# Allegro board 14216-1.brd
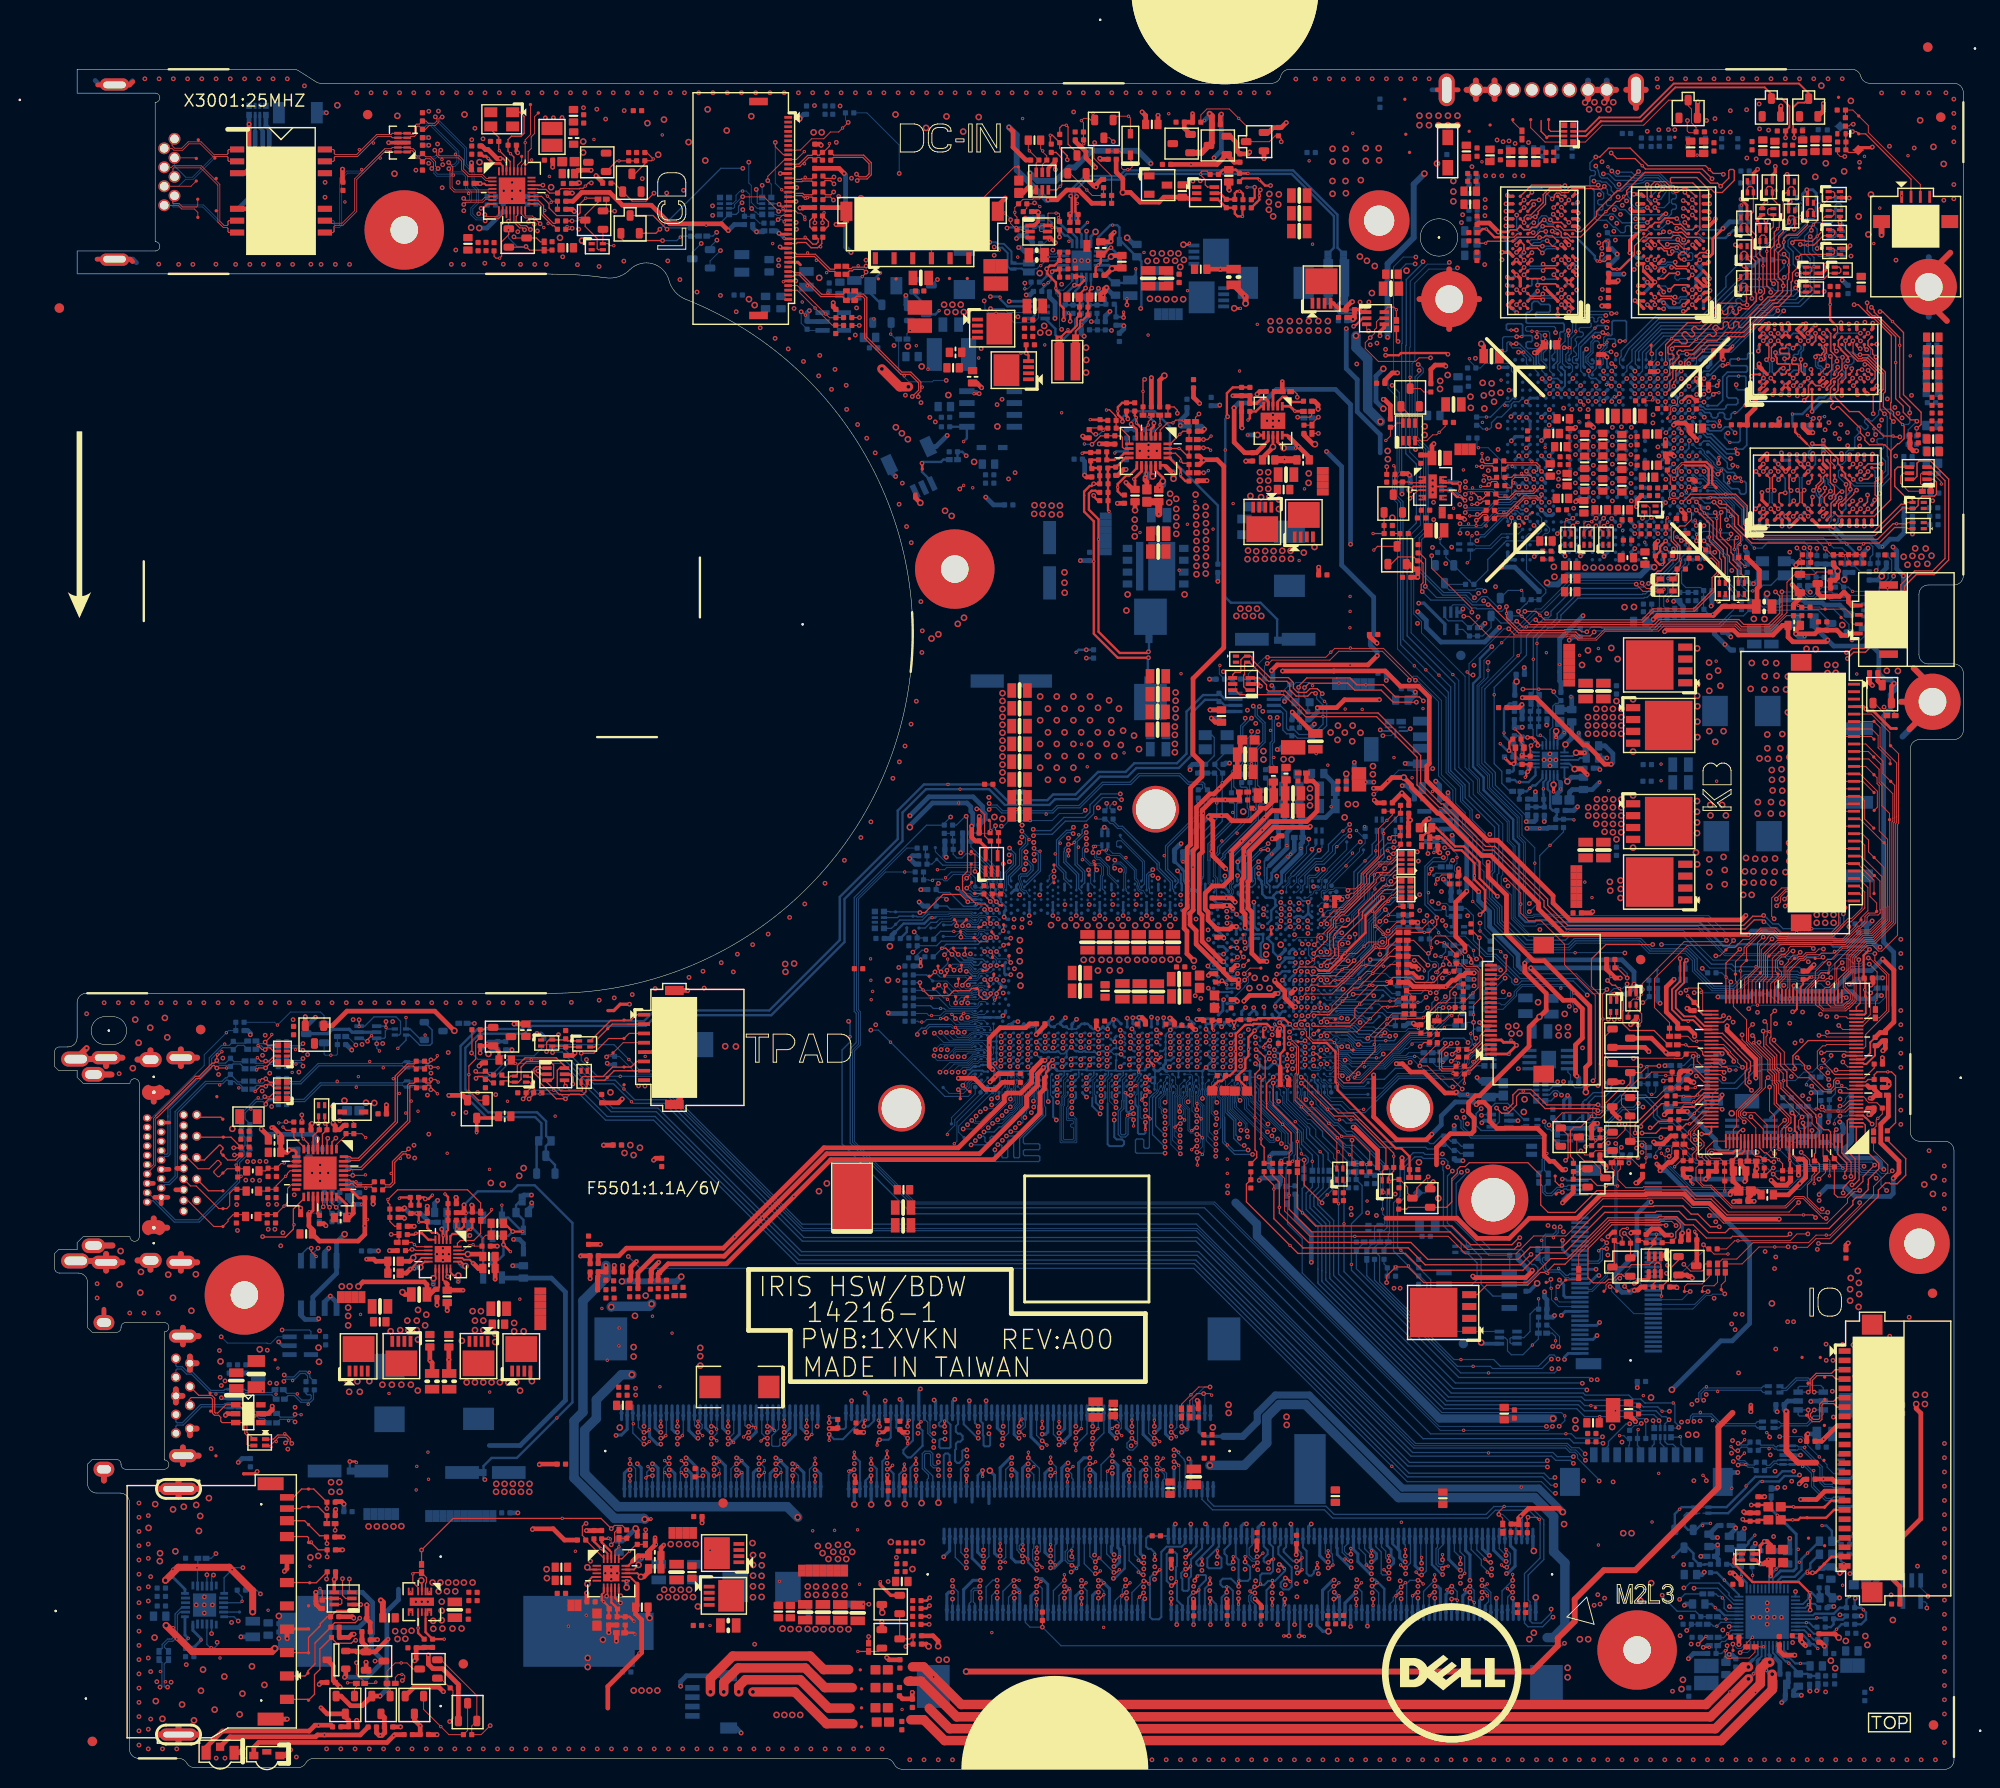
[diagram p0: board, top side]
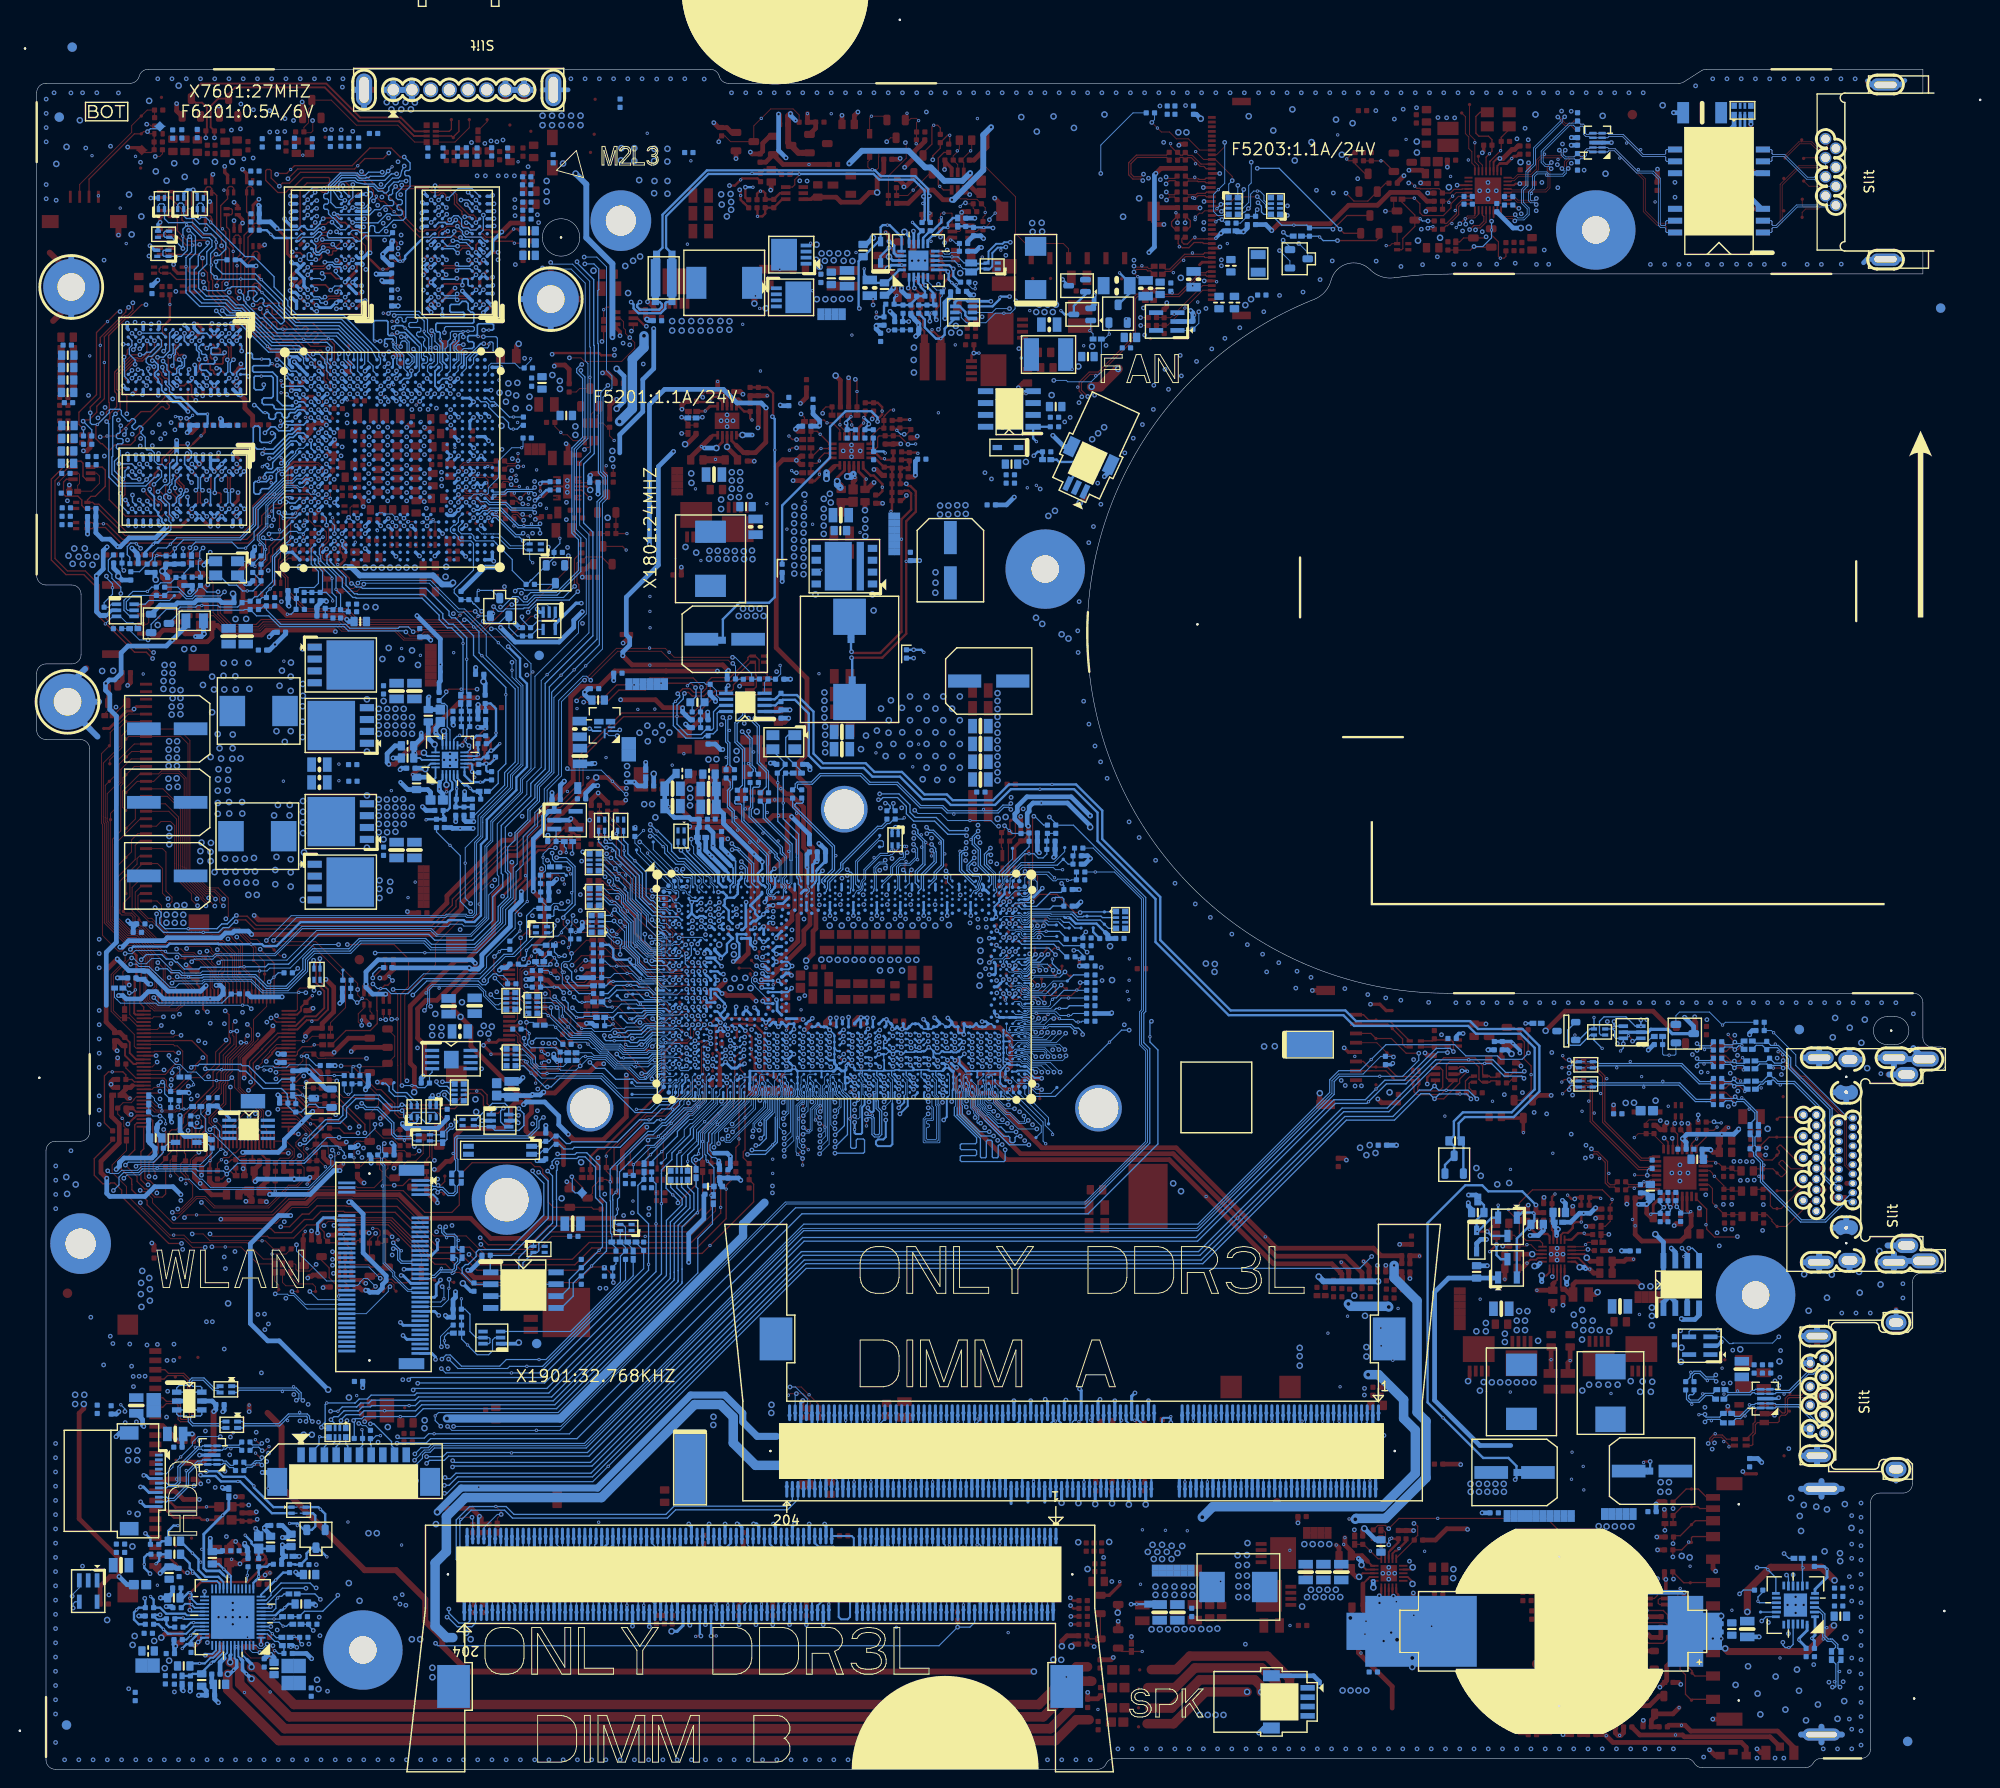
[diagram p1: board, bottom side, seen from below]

Outline 204.2 x 181.97 mm; copper layers: TOP, L2VCC, L3, L4, L5GND, BOTTOM. Coordinates in mm from the lower left corner of the outline.
Outline path: 0,76.82 0,75.22 0.4,74.82 2.4,74.82 2.4,74.07 3.05,73.42 8.05,73.42 arc(8.55,73.92) 9.05,73.42 9.05,57.02 arc(8.55,56.52) 8.05,57.02 3.05,57.02 2.4,56.37 2.4,55.62 0.4,55.62 0,55.22 0,53.62 arc(0.15,53.27) 0.5,53.12 2.52,53.12 arc(3.23,52.83) 3.52,52.12 3.52,47.27 4.02,46.77 6.6,46.77 arc(6.97,46.93) 7.1,47.32 arc(7.25,47.67) 7.6,47.82 11.72,47.82 arc(12.22,47.32) 11.72,46.82 11.72,33.12 arc(12.22,32.62) 11.72,32.12 7.6,32.12 arc(7.25,32.27) 7.1,32.62 arc(6.97,33.01) 6.6,33.17 4.02,33.17 3.52,32.67 3.52,30.57 arc(3.81,29.86) 4.52,29.57 7,29.57 arc(7.71,29.28) 8,28.57 8,2.17 arc(8.29,1.46) 9,1.17 13.27,1.17 arc(13.77,1.04) 14.13,0.67 arc(14.5,0.3) 15,0.17 26,0.17 arc(26.5,0.3) 26.87,0.67 arc(27.23,1.04) 27.73,1.17 88.88,1.17 arc(89.42,1.01) 89.79,0.58 arc(90.16,0.16) 90.7,0 202.2,0 arc(202.91,0.29) 203.2,1 203.2,66.23 arc(202.91,66.94) 202.2,67.23 199.53,67.23 arc(198.82,67.52) 198.53,68.23 198.53,109.23 arc(198.82,109.94) 199.53,110.23 203.2,110.23 arc(203.91,110.52) 204.2,111.23 204.2,117.32 arc(203.91,118.03) 203.2,118.32 200.45,118.32 arc(199.74,118.61) 199.45,119.32 199.45,125.77 arc(199.74,126.48) 200.45,126.77 203.2,126.77 arc(203.91,127.06) 204.2,127.77 204.2,179.47 arc(203.91,180.18) 203.2,180.47 194.2,180.47 arc(193.59,180.68) 193.23,181.22 arc(192.88,181.76) 192.26,181.97 132.14,181.97 arc(131.52,181.76) 131.17,181.22 arc(130.81,180.68) 130.2,180.47 28.49,180.47 arc(28.21,180.51) 27.95,180.63 26.1,181.81 arc(25.84,181.93) 25.56,181.97 2.4,181.97 2.4,179.42 10.75,179.42 arc(11.25,178.92) 10.75,178.42 10.75,163.52 arc(11.25,163.02) 10.75,162.52 2.4,162.52 2.4,160.07 52.55,160.07 arc(52.93,160.06) 53.3,160.04 arc(56.13,159.95) 58.95,159.65 arc(60.34,159.77) 61.52,160.51 arc(63.95,161.16) 65.72,159.38 arc(66.37,158.15) 67.51,157.35 arc(91.11,114.33) 53.3,83.07 arc(52.93,83.06) 52.55,83.07 3.4,83.07 arc(2.69,82.78) 2.4,82.07 2.4,78.32 arc(2.11,77.61) 1.4,77.32 0.5,77.32 arc(0.15,77.17) 0,76.82 ; 5.4,80.57 6.2,80.57 arc(7.7,79.07) 6.2,77.57 5.4,77.57 arc(3.9,79.07) 5.4,80.57 ; 18.85,50.77 arc(20.3,52.22) 21.75,50.77 arc(20.3,49.32) 18.85,50.77 ; 35.95,164.77 arc(37.4,166.22) 38.85,164.77 arc(37.4,163.32) 35.95,164.77 ; 88.5,70.77 arc(90.6,72.87) 92.7,70.77 arc(90.6,68.67) 88.5,70.77 ; 94.85,128.47 arc(96.3,129.92) 97.75,128.47 arc(96.3,127.02) 94.85,128.47 ; 115.7,102.77 arc(117.8,104.87) 119.9,102.77 arc(117.8,100.67) 115.7,102.77 ; 140.1,165.77 arc(141.7,167.37) 143.3,165.77 arc(141.7,164.17) 140.1,165.77 ; 142.9,70.77 arc(145,72.87) 147.1,70.77 arc(145,68.67) 142.9,70.77 ; 146.1,163.97 arc(148.1,165.97) 150.1,163.97 arc(148.1,161.97) 146.1,163.97 ; 151.6,60.97 arc(153.9,63.27) 156.2,60.97 arc(153.9,58.67) 151.6,60.97 ; 167.85,12.77 arc(169.3,14.22) 170.75,12.77 arc(169.3,11.32) 167.85,12.77 ; 197.9,56.27 arc(199.5,57.87) 201.1,56.27 arc(199.5,54.67) 197.9,56.27

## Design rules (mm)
constraint set DEFAULT: min track width 0.127, pair gap 0.102
net group AUDIO_12MIL: nets CPVEE V3D3_STB
net group CLK_PCI_KBC: nets CLK_PCI_KBC CLK_PCI_KBC_R
net group CLK_PCI_LPC: nets CLK_PCI_LPC CLK_PCI_LPC_R
net group CODEC_BITCLK_R: nets CODEC_BITCLK_R HDA_CODEC_BITCLK
net group CODEC_SDOUT_R: nets CODEC_SDOUT_R HDA_CODEC_SDOUT
net group CPU_RXN_C_DGPU_TXN0: nets CPU_RXN_C_DGPU_TXN0 DGPU_TXN_CPU_RXN0
net group CPU_RXN_C_DGPU_TXN1: nets CPU_RXN_C_DGPU_TXN1 DGPU_TXN_CPU_RXN1
net group CPU_RXN_C_DGPU_TXN2: nets CPU_RXN_C_DGPU_TXN2 DGPU_TXN_CPU_RXN2
net group CPU_RXN_C_DGPU_TXN3: nets CPU_RXN_C_DGPU_TXN3 DGPU_TXN_CPU_RXN3
net group CPU_RXP_C_DGPU_TXP0: nets CPU_RXP_C_DGPU_TXP0 DGPU_TXP_CPU_RXP0
net group CPU_RXP_C_DGPU_TXP1: nets CPU_RXP_C_DGPU_TXP1 DGPU_TXP_CPU_RXP1
net group CPU_RXP_C_DGPU_TXP2: nets CPU_RXP_C_DGPU_TXP2 DGPU_TXP_CPU_RXP2
net group CPU_RXP_C_DGPU_TXP3: nets CPU_RXP_C_DGPU_TXP3 DGPU_TXP_CPU_RXP3
net group CRT_B: nets CRT_B DP_CRT_B
net group CRT_G: nets CRT_G DP_CRT_G
net group CRT_HSYNC_CON: nets CRT_HSYNC_CON DP_CRT_HSYNC_CON
net group CRT_R: nets CRT_R DP_CRT_R
net group CRT_VSYNC_CON: nets CRT_VSYNC_CON DP_CRT_VSYNC_CON
net group DDR3_A_ODT10: nets M_A_DIMA_ODT0 M_A_DIMA_ODT1
net group DDR3_B_ODT10: nets M_B_DIMB_ODT0 M_B_DIMB_ODT1
net group DGPU_RXN_CPU_TXN0: nets DGPU_RXN_C_CPU_TXN0 DGPU_RXN_CPU_TXN0
net group DGPU_RXN_CPU_TXN1: nets DGPU_RXN_C_CPU_TXN1 DGPU_RXN_CPU_TXN1
net group DGPU_RXN_CPU_TXN2: nets DGPU_RXN_C_CPU_TXN2 DGPU_RXN_CPU_TXN2
net group DGPU_RXN_CPU_TXN3: nets DGPU_RXN_C_CPU_TXN3 DGPU_RXN_CPU_TXN3
net group DGPU_RXP_CPU_TXP0: nets DGPU_RXP_C_CPU_TXP0 DGPU_RXP_CPU_TXP0
net group DGPU_RXP_CPU_TXP1: nets DGPU_RXP_C_CPU_TXP1 DGPU_RXP_CPU_TXP1
net group DGPU_RXP_CPU_TXP2: nets DGPU_RXP_C_CPU_TXP2 DGPU_RXP_CPU_TXP2
net group DGPU_RXP_CPU_TXP3: nets DGPU_RXP_C_CPU_TXP3 DGPU_RXP_CPU_TXP3
net group EDP_AUX: nets EDP_AUX EDP_AUX_DP
net group EDP_AUX#: nets EDP_AUX# EDP_AUX_DN
net group EDP_TX0: nets EDP_TX0 EDP_TX0_DP
net group EDP_TX0#: nets EDP_TX0# EDP_TX0_DN
net group EDP_TX1: nets EDP_TX1 EDP_TX1_DP
net group EDP_TX1#: nets EDP_TX1# EDP_TX1_DN
net group FAN_TACH: nets FAN_TACH1 FAN_TACH1_C
net group FBA_VREF: nets FBA_VREF_0 FBA_VREF_1
net group H_CPU_SVIDCLK: nets H_CPU_SVIDCLK PWR_VCC_SCLK
net group H_CPU_SVIDDAT: nets H_CPU_SVIDDAT PWR_VCC_SDA
net group LAN_TXN_C_PCH_RXN4: nets LAN_TXN_C_PCH_RXN4 PCIE_PRX_LANTX_N4
net group LAN_TXP_C_PCH_RXP4: nets LAN_TXP_C_PCH_RXP4 PCIE_PRX_LANTX_P4
net group PCH_DPB_AUXN: nets PCH_DPB_AUXN PCH_DPC_AUXN_U
net group PCH_DPB_AUXP: nets PCH_DPB_AUXP PCH_DPC_AUXP_U
net group PCIE_PRX_WLANTX_N3: nets PCIE_PRX_WLANTX_N3 PCIE_PRX_WLANTX_N3_R
net group PCIE_PRX_WLANTX_P3: nets PCIE_PRX_WLANTX_P3 PCIE_PRX_WLANTX_P3_R
net group PCIE_PTX_LANRX_N4: nets PCIE_PTX_LANRX_N4 PCIE_PTX_LANRX_N4_C
net group PCIE_PTX_LANRX_P4: nets PCIE_PTX_LANRX_P4 PCIE_PTX_LANRX_P4_C
net group PCIE_PTX_WLANRX_N3: nets PCIE_PTX_WLANRX_N3 PCIE_PTX_WLANRX_N3_C
net group PCIE_PTX_WLANRX_P3: nets PCIE_PTX_WLANRX_P3 PCIE_PTX_WLANRX_P3_C
net group PECI-MW: nets H_PECI PECI
net group POWER_15M: nets Q6205_Q TP_ON#_S
net group PWR_VCC_FB: nets PWR_VCC_FB VCC_SENSE
net group REF10M: nets KBC_VCORF PROC_OPI_COMP3
net group SATA_PRX_ODDTX_N1: nets SATA_PRX_ODDTX_N1 SATA_RXN2_R
net group SATA_PRX_ODDTX_P1: nets SATA_PRX_ODDTX_P1 SATA_RXP2_R
net group SATA_PTX_ODDRX_N1: nets SATA_PTX_ODDRX_N1 SATA_TXN2_R
net group SATA_PTX_ODDRX_P1: nets SATA_PTX_ODDRX_P1 SATA_TXP2_R
net group SD_CD#: nets SD_CD# SD_CD_R#
net group SD_CLK: nets SD_CLK SD_CLK_5170
net group SD_WP: nets SD_WP SD_WP_5170
net group T8-MW: nets VD_IN1 VD_IN1_C
net group THERM_10M: nets FON# VD1_EN#
net group USB3_PTX_CRX_N0: nets USB3_PTX_CRX_N0 USB3_PTX_CRX_N0_R
net group USB3_PTX_CRX_P0: nets USB3_PTX_CRX_P0 USB3_PTX_CRX_P0_R
net group USB_CAMERA_EDP: nets USB_CAMERA_EDP USB_PP4
net group USB_CAMERA_EDP#: nets USB_CAMERA_EDP# USB_PN4
net group USB_PN0: nets USB_PN0 USB_PN0_C
net group USB_PN5: nets USB_PN5 USB_PN5_R
net group USB_PN6: nets USB_PN6 USB_PN6_TPNL
net group USB_PN7: nets USB_PN7 USB_PN7_R
net group USB_PP0: nets USB_PP0 USB_PP0_C
net group USB_PP5: nets USB_PP5 USB_PP5_R
net group USB_PP6: nets USB_PP6 USB_PP6_TPNL
net group USB_PP7: nets USB_PP7 USB_PP7_R
net group AUDIO_BEEP_10MIL: nets AUD_HP1_JACK_L AUD_HP1_JACK_L1 AUD_HP1_JACK_R AUD_HP1_JACK_R1 AUD_PC_BEEP AUD_PC_BEEP_C AUD_PORTA_L_R_B AUD_PORTA_R_R_B AUD_SENSE AUD_SENSE_A AUD_VREF CBN HDA_SPKR HDA_SPKR_R JACK_PLUG KBC_BEEP KBC_BEEP_R LINE1-L_C LINE1-L_R LINE1_L LINE1_R LINE1_VREFO_L LINE1_VREFO_R MIC2_VREFO
net group CARD_12MIL: nets RREF RSET SDREFG V18
net group CFG-MW: nets CFG0 CFG1 CFG2 CFG3 CFG4 CFG5 CFG6 CFG7 CFG8 CFG9 CFG10 CFG11 CFG12 CFG13 CFG14 CFG15 CFG16 CFG17 CFG18 CFG19
net group CL-MW: nets TP_CL_CLK TP_CL_DATA TP_CL_RST#
net group CLK-MW: nets CLK_DP2VGA PEXTSTCLK_OUT PEXTSTCLK_OUT# SUS_CLK SUS_CLK_PCH SUSCLK_KBC VIDEO_CLK_XTAL_SS
net group COMP_20MIL: nets CFG_RCOMP EDP_COMP PCH_OPIRCOMP PCIE_RCOMP PROC_OPI_COMP SATA_IREF SATA_RCOMP SM_RCOMP_0 SM_RCOMP_1 SM_RCOMP_2 TD_IREF USB_COMP XCLK_BIASREF
net group CPU-MW: nets H_PROCHOT# H_PROCHOT#_EC H_PROCHOT#_R PQ4405_3 PROCHOT_EC VGA_CORE_VID
net group DDC_CLK_HDMI: nets DDC_CLK_HDMI
net group DDC_DATA_HDMI: nets DDC_DATA_HDMI
net group GND: nets GND_R1 GND_R2 MIC_GND
net group H_CPU_SVIDALRT#: nets H_CPU_SVIDALRT# PWR_VCC_ALERT# VR_SVID_ALERT#
net group HDA_CODEC_RST#: nets HDA_CODEC_RST#
net group HDA_CODEC_SDIN0: nets HDA_SDIN0
net group HDA_CODEC_SYNC: nets HDA_CODEC_SYNC
net group HDMI_CLK: nets HDMI_CLK HDMI_CLK_R HDMI_CLK_R_C
net group HDMI_CLK#: nets HDMI_CLK# HDMI_CLK#_R HDMI_CLK#_R_C
net group HDMI_CRT_N0: nets HDMI_CRT_N0 HDMI_DATA2# HDMI_DATA2#_R HDMI_DATA2#_R_C PCH_DPC_N0_U
net group HDMI_CRT_N1: nets HDMI_CRT_N1 HDMI_DATA1# HDMI_DATA1#_R HDMI_DATA1#_R_C PCH_DPC_N1_U
net group HDMI_CRT_P0: nets HDMI_CRT_P0 HDMI_DATA2 HDMI_DATA2_R HDMI_DATA2_R_C PCH_DPC_P0_U
net group HDMI_CRT_P1: nets HDMI_CRT_P1 HDMI_DATA1 HDMI_DATA1_R HDMI_DATA1_R_C PCH_DPC_P1_U
net group HDMI_DATA0: nets HDMI_DATA0 HDMI_DATA0_R HDMI_DATA0_R_C
net group HDMI_DATA0#: nets HDMI_DATA0# HDMI_DATA0#_R HDMI_DATA0#_R_C
net group JTAG: nets PCH_JTAG_TCK PCH_JTAG_TDI PCH_JTAG_TDO PCH_JTAG_TMS PCH_JTAG_TRST#
net group KB: nets KB_BL_CTRL KCOL0 KCOL1 KCOL2 KCOL3 KCOL4 KCOL5 KCOL6 KCOL7 KCOL8 KCOL9 KCOL10 KCOL11 KCOL12 KCOL13 KCOL14 KCOL15 KCOL16 KROW0 KROW1 KROW2 KROW3 KROW4 KROW5 KROW6 KROW7
net group LAN_MDI0N: nets MDO0-
net group LAN_MDI0P: nets MDO0+
net group LAN_MDI1N: nets MDO1-
net group LAN_MDI1P: nets MDO1+
net group LAN_MDI2N: nets MDO2-
net group LAN_MDI2P: nets MDO2+
net group LAN_MDI3N: nets MDO3-
net group LAN_MDI3P: nets MDO3+
net group LCD_BKLT-MW: nets BKLT_CTRL EC_BRIGHTNESS EDP_BKLT_CTRL EDP_BRIGHTNESS L_BKLT_CTRL LCD_BRIGHTNESS
net group LED: nets BATT_WHITE_LED# BATT_WHITE_LED_R# CAP_LED# CAP_LED_R# CHG_AMBER_LED# CHG_AMBER_LED_R# SATA_LED# SATA_LED#_B SATA_LED#_R
net group LED_20MIL: nets AMBER_LED_BAT BAT_AMBER BAT_WHITE CAP_LED CAP_LED_Q SATA_LED SATA_LED_R WHITE_LED_BAT
net group LPC-MWS: nets INT_SERIRQ LPC_AD0 LPC_AD1 LPC_AD2 LPC_AD3 LPC_FRAME# LPC_FRAME#_DEBUG LPC_LAD0_PCH LPC_LAD0_R LPC_LAD1_PCH LPC_LAD1_R LPC_LAD2_PCH LPC_LAD2_R LPC_LAD3_PCH LPC_LAD3_R LPC_LFRAME#_PCH
net group OTHER_4MIL: nets 1D05V_VGA_S0_DISCHG AC_IN# AC_PRESENT AD+_G_1 AD_IA AD_IA_HW AD_IA_HW2 ALERT# AMP_MUTE# BAT_IN# BATLOW# BLON_OUT BLON_OUT_C BLUETOOTH_EN BLUETOOTH_EN_NGFF BOARD_ID2 BOARD_ID3 BUFRST# CAMERA_PWR_EN CARD_PWR_EN CLK_PCIE_WLAN_REQ3# CLK_PCIE_WLAN_REQ# COLOR_ENGINE COMBO-GPI CPU_ID CRT_PCH_HPD DBC_EN DBC_EN_R DC_TEST_A3_B3 DC_TEST_A61_B61 DC_TEST_AY2_AW2 DC_TEST_AY3_AW3 DC_TEST_AY61_AW61 DC_TEST_AY62_AW62 DC_TEST_B62_B63 DC_TEST_C1_C2 DGPU_PWR_EN# DSWODVREN E51_RX1 E51_RX2 E51_TX1 E51_TX2 E51_TXD EAPD# EC_SCI# EC_SMI# EC_SWI# ECRST# ECSCI#_KBC ECSMI#_KBC ECSWI#_KBC EDP_HPD EDP_HPD_CONN EDP_SPARE FB_VREF FBA_DEBUG0 FBA_DEBUG1 H_CATERR# H_RCIN# H_THERMTRIP# H_THERMTRIP_EN HDD_DEVSLP HDD_DEVSLP_R HDMI_CRT_DET HDMI_HPD_B HDMI_HPD_E HPD_HDMI_CON HSIOPC HSIOPC_R HVM_CLK HVM_CLK# IFPAB_IOVDD IFPAB_PLLVDD IFPC_IOVDD IFPC_PLLVDD IFPD_IOVDD IFPD_PLLVDD IFPEF_IOVDD IFPEF_PLLVDD INT_TP# INT_TP#_C ISOLATE# JDREF KB_DET# KB_LED_BL_DET KB_LED_DET_C KBC_ON#_GATE KBC_ON#_GATE_L KBC_PWRBTN# L_BKLT_EN L_BKLT_EN_EC LCD_TST LCD_TST_C LCD_TST_EN LCDVDD_EN LDO_EN LED0 LED1 LED2 LID_CLOSE# LID_CLOSE#_C LPSS_GSPI0_MOSI_BBS0_R LPSS_SDIO_D0_CMNHDR MCP_GPIO11 MCP_GPIO12 MCP_GPIO13 MCP_GPIO14 MCP_GPIO15 MCP_GPIO26 MCP_GPIO27 MCP_GPIO28 MCP_GPIO36 MCP_GPIO44 MCP_GPIO56 MCP_GPIO57 MCP_GPIO58 MCP_GPIO73 MCP_GPIO76 MCP_R MCP_TESTLOW1 MCP_TESTLOW2 MCP_TESTLOW3 MCP_TESTLOW4 ME_UNLOCK MODEL_ID_DET N12P_JTAG_TCK N12P_JTAG_TDI N12P_JTAG_TDO N12P_JTAG_TMS N12P_JTAG_TRST N12P_XTAL_OUTBUFF P2800_VGA_DXN P2800_VGA_DXP PANEL_SIZE_ID PANEL_SIZE_ID_CONN PCB_VER_AD PCH_INTVRMEN PCH_THERMTRIP PCH_WAKE# PCI_PME# PD4403_A PD4403_K PEX_TERMP PIRQA# PIRQB# PIRQC# PIRQD# PLT_RST# PLT_RST#_EC PLT_RST_NGFF# PM_CLKRUN# PM_CLKRUN#_EC PM_PWRBTN# PM_SLP_A# PM_SLP_SUS# PQ4405_2 PQ4405_5 PQ4405_6 PQ4406_G PQ4408_C PQ4408_E PROJECT_ID1 PROJECT_ID2 PS_ID_R PSID_EC PSL_IN1# PSL_IN2# PSL_OUT# PWR_5V_VCLK PWR_CHG_ACOK PWR_CHG_AD_OFF PWR_CHG_AD_OFF_R PWR_CHG_ILIM Q402_1 Q7601_G RRX RSVDA51 RSVDAU63 RSVDAV63 RSVDB51 RSVDC62 RSVDC63 RSVDL60 RSVDN59 RSVDN61 RSVDP60 RSVDP61 RTC_DET# SA0_DIMA SA0_DIMB SA1_DIMA SA1_DIMB SM_INTRUDER# TESTMODE TP_DC_TEST_A4 TP_DC_TEST_A60 TP_DC_TEST_A62 TP_DC_TEST_AV1 TP_DC_TEST_AW1 TP_DC_TEST_AW63 TP_DC_TEST_AY60 TP_DC_TEST_B2 TP_HDA_DOCK_EN# TP_M_A_DIMA_ODT0 TP_M_B_DIMB_ODT0 TP_RESET TP_RS TP_V1.05S_APLLOPI TP_V1.05S_AXCK_DCB TP_V1.05S_SSCF100 TP_V1.05S_SSCFF TP_VCCAPLLOPI_VAL TP_VCCIO_OUT USB_OC#0_1 USB_OC#2_3 USB_OC#4_5 USB_OC#6_7 VGA_CORE_DISCHG VRAM_ID1 VRAM_ID2 WIFI_RF_EN WLAN_DISABLE#1 WLAN_PLT_RST# WLAN_WAKE
net group PLATFORM: nets 1D05V_VGA_EN 1D05V_VTT_PWRGD 1D35V_ENABLE 1D35V_ENABLE_RC 1D35V_VGA_EN 1D35V_VGA_EN# 1D35V_VTT_PWRGD 3V5V_S0_ON 3V_5V_EN 3V_5V_POK 3V_5V_POK# 3V_5V_POK_C ALL_SYS_PWRGD CLK_LAN_REQ4#_R CLK_LAN_REQ#_EN CLK_PCIE_LAN_REQ4# CLK_PCIE_REQ# DDR3_DRAMRST# DDR_PG_CTRL DDR_PG_CTRL_R DDR_VTT_PG_CTRL DDR_VTT_PG_CTRL_R DGPU_HOLD_RST# DGPU_PWR_EN DGPU_PWROK DGPU_PWROK_KBC DS3_PWRCTL EDP_VDD_EN GC6_FB_EN GC6_FB_EN_GPU GC6_FB_EN_KBC GC6_FB_EN_MCP GPIO5_GC6_PWR_EN GPIO5_GC6_PWR_EN# GPIO5_GC6_PWR_EN_GPU GPIO5_GC6_PWR_EN_R# GPIO9_ALERT GPIO10_FBVREF GPU_CLKREQ# GPU_EVENT# GPU_EVENT_GPU# GPU_EVENT_MCP# GPU_PEX_RST# GPU_PEX_RST_D# GPU_PEX_RST_HOLD GPU_PEX_RST_HOLD_GPU# H_CPUPWRGD H_VCCST_PWRGD H_VR_ENABLE IMVP_PWRGD IMVP_PWRGD_R KBC_DPWROK KBC_PWRBTN#_C LAN_ENABLE_R_C MCP_GPIO8 MCP_GPIO46 MCP_GPIO55 MPWROK OVERT# OVERT_GPU# PCH_DPWROK PCH_PWROK PCH_SLP_S0# PCH_SLP_WLAN# PCI_PLTRST# PCIE_WAKE# PEG_CLKREQ# PLT_RST#_DEBUG PLT_RST#_LAN PM_LAN_ENABLE PM_LAN_ENABLE_R PM_PCH_PWROK PM_RSMRST# PM_SLP_LAN# PM_SLP_S3# PM_SLP_S4# PM_SLP_S5# PM_SUS_STAT# PM_SUSACK# PM_SUSACK#_R PM_SUSWARN# PM_SUSWARN#_R PS_S3CNTRL PU4401_6 PWR_1D5V_EN PWR_1D35V_EN PWR_3D3V_EN2 PWR_5V_EN1 PWR_5V_EN1_R PWR_LEVEL PWR_VCC_EN PWR_VCC_POK ROM_CS# ROM_SCLK ROM_SI ROM_SO RSMRST#_KBC RTC_RST# RTCRST_ON S5_ENABLE SATA_ODD_DA# SATA_ODD_DA#_C SATA_ODD_PRSNT# SATA_ODD_PWRGT SM_DRAMRST# SRTC_RST# STRAP0 STRAP1 STRAP2 STRAP3 STRAP4 STRAP_REF0_GND_N9 SYS_PEX_RST_MON# SYS_PEX_RST_MON_GPU# SYS_PWROK TOUCH_PANEL_INTR# TOUCH_PANEL_INTR_KBC# TP_LOCK# TP_LOCK#_C TP_ON# TP_ON#_GATE TP_WAKE_KBC# USB_PWR_EN# VGA_CORE_PSI VIDEO_THERM_OVERT#
net group POWER_10M: nets 3V5V_CT1 3V5V_CT2 +3.3A_DSW_PRTCSUS +3V_1D5V_AVDD +PCH_VCCDSW +V1.05A_SUS_PCH +V1.05A_USB2SUS +V1.05A_VCCUSB3SUS +V3.3A_1.5A_HDA +V3.3A_DSW_P +V3.3S_1.8S_LPSS_SDIO +V3.3S_PCORE +VCCRTCEXT +VCHGR_R AD+_G_2 BMON BOOST_MODE# BOOST_MON_1 DCBATOUT_R EC_VBKUP FAN1_DAC_1 FB_CLAM FBA_ZQ0 FBA_ZQ1 FBA_ZQ2 FBA_ZQ3 FBA_ZQ5 FBA_ZQ6 FBA_ZQ7 FBA_ZQ8 ISUM_R_R LDO1_CAP LDO2_CAP LDO3_CAP MIC_CAP PCH_VCCDSW_R PHASE_R_R PQ4008_2 PU4401_4 PU4401_5 PWR_1D05V_CCM PWR_1D05V_TRIP PWR_1D35V_VDDQS PWR_VCC_COMP PWR_VCC_COMP_RC PWR_VCC_ISUMN PWR_VCC_ISUMP PWR_VCC_NTC PWR_VCC_NTC_R PWR_VCC_PRGM1 PWR_VCC_PRGM2 PWR_VGA_CORE_EN PWR_VGA_CORE_PSI PWR_VGA_CORE_REFIN PWR_VGA_CORE_VID PWR_VGA_CORE_VREF Q6204_G REFIN_VREF VTT_CT_3VC_1 VTT_CT_105VC_2 XDP_PWR_DEBUG
net group POWER_10M_POWER: nets 3V_FEEDBACK 15V_PWR AD_OFF_L BOOST_10V BST15V_1 BST15V_2 ISUM_R_C PHASE1G PQ3809_D PR4601_1 PWR_1D05V_PWR PWR_1D35V_MODE PWR_1D35V_REFIN PWR_1D35V_TRIP PWR_1D35V_VREF PWR_3D3V_CS2 PWR_3D3V_FB2 PWR_3D3V_FB2_R PWR_5V_CS1 PWR_5V_FB1 PWR_5V_FB1_R PWR_CHG_ACDET PWR_CHG_BTST_R PWR_CHG_CMPIN PWR_CHG_CMPIN_R PWR_CHG_CMPIN_RR PWR_CHG_CMPOUT PWR_CHG_IFAULT PWR_CHG_IOUT PWR_CHG_REGN PWR_CHG_VCC PWR_VCC_FB_RC PWR_VCC_IMON PWR_VGA_CORE_REFADJ PWR_VGA_CORE_SS PWR_VGA_CORE_TON PWR_VGA_CORE_TON_1
net group POWER_20M: nets 3D3V_AUX_KBC_VCC 3D3V_AUX_S5 15V_S5 +RTC_VCC +V1.05A_AOSCSUS +V1.05S_AIDLE +V1.05S_APLLOPI +V1.05S_ASATA3PLL +V1.05S_AUSB3PLL +V1.05S_AXCK_DCB +V1.05S_AXCK_LCPLL +V1.05S_SSCF100 +V1.05S_SSCFF +V_SM_VREF_CNT +V_VREF_PATH1 +V_VREF_PATH2 +V_VREF_PATH3 +VCCIOA_OUT DDR_WR_VREF01 DDR_WR_VREF02 EC_VTT MCT0 MCT1 MCT2 MCT3 PR4605_2 PWR_1D05V_BOOT PWR_1D05V_EN PWR_1D05V_FB PWR_1D05V_PWRGD PWR_1D35V_VBST PWR_3D3V_VBST2 PWR_3D3V_VBST2_1 PWR_5V_VBST1 PWR_5V_VBST1_1 PWR_5V_VO1 PWR_CHG_BTST PWR_DEBUG RTC_PWR VBAT
net group POWER_20M_POWER: nets 3D3V_PWR_2 5V_PWR_2 +3V_AVDD +5V_KB_BL AVCC33 KB_BL_CTRL# PWR_3D3V_SNUB PWR_5V_SNUB PWR_CHG_SNUB PWR_VGA_CORE_BOOT1 PWR_VGA_CORE_BOOT1_1 PWR_VGA_CORE_BOOT2 PWR_VGA_CORE_BOOT2_1 VCCK_12 VDD_DAC_33
net group POWER_25M: nets PQ3802_1 PS_ID PSID_DISABLE#_R_C
net group POWER_40M: nets DIS_1D35V_VGA_S0 FB_CAL_PD_VDDQ FB_CAL_PU_GND FB_CAL_TERM_GND PWR_1D05V_BOOT_R PWR_VCC_BOOT PWR_VCC_BOOT_RC
net group POWER_160M: nets RT8812_PVCC
net group SATA3_PRX_HDDTX_N0: nets SATA3_PRX_HDDTX_N0
net group SATA3_PRX_HDDTX_P0: nets SATA3_PRX_HDDTX_P0
net group SATA3_PTX_HDDRX_N0: nets SATA3_PTX_HDDRX_N0
net group SATA3_PTX_HDDRX_P0: nets SATA3_PTX_HDDRX_P0
net group SMBUS_50OHM-MWS: nets DMIC_CLK_R DMIC_DATA_R I2C0_SCL I2C0_SDA I2C1_SCL I2C1_SCL_R I2C1_SDA I2C1_SDA_R I2CA_SCL I2CA_SDA I2CB_SCL I2CB_SDA I2CC_SCL I2CC_SDA SMB_CLK SMB_DATA SMBC_THERM_NV SMBD_THERM_NV SML0_CLK SML0_DATA SML1_CLK THM_SML1_CLK THM_SML1_DATA TPCLK TPCLK_C TPDATA TPDATA_C
net group SPI-MWS: nets EC_SPI_CLK_C EC_SPI_CS#_C EC_SPI_DI_C EC_SPI_DO_C PCH_SPI_CLK PCH_SPI_CS0# PCH_SPI_DQ2 PCH_SPI_DQ3 PCH_SPI_SI PCH_SPI_SO SPI_CLK_R SPI_CS0#_R SPI_HOLD# SPI_SI_R SPI_SO_R SPI_WP#
net group THERM_SHUTDOWN: nets OVER_CURRENT_P8# P_H_S# PURE_HW_SHUTDOWN# T_CRIT# THERM_SYS_SHDN# VD_OUT1#
net group USB3_PRX_CTX_N0: nets USB3_PRX_CTX_N0
net group USB3_PRX_CTX_P0: nets USB3_PRX_CTX_P0
net group VRAM_CMD-MWS: nets FBA_CMD0 FBA_CMD1 FBA_CMD2 FBA_CMD3 FBA_CMD4 FBA_CMD5 FBA_CMD6 FBA_CMD7 FBA_CMD8 FBA_CMD9 FBA_CMD10 FBA_CMD11 FBA_CMD12 FBA_CMD13 FBA_CMD14 FBA_CMD15 FBA_CMD16 FBA_CMD17 FBA_CMD18 FBA_CMD19 FBA_CMD20 FBA_CMD21 FBA_CMD22 FBA_CMD23 FBA_CMD24 FBA_CMD25 FBA_CMD26 FBA_CMD27 FBA_CMD28 FBA_CMD29 FBA_CMD30 FBA_CMD31
net group VRAM_DBI-MW: nets FBA_DQM0 FBA_DQM1 FBA_DQM2 FBA_DQM3 FBA_DQM4 FBA_DQM5 FBA_DQM6 FBA_DQM7
net group VRAM_DQ-MW: nets FBA_D0 FBA_D1 FBA_D2 FBA_D3 FBA_D4 FBA_D5 FBA_D6 FBA_D7 FBA_D8 FBA_D9 FBA_D10 FBA_D11 FBA_D12 FBA_D13 FBA_D14 FBA_D15 FBA_D16 FBA_D17 FBA_D18 FBA_D19 FBA_D20 FBA_D21 FBA_D22 FBA_D23 FBA_D24 FBA_D25 FBA_D26 FBA_D27 FBA_D28 FBA_D29 FBA_D30 FBA_D31 FBA_D32 FBA_D33 FBA_D34 FBA_D35 FBA_D36 FBA_D37 FBA_D38 FBA_D39 FBA_D40 FBA_D41 FBA_D42 FBA_D43 FBA_D44 FBA_D45 FBA_D46 FBA_D47 FBA_D48 FBA_D49 FBA_D50 FBA_D51 FBA_D52 FBA_D53 FBA_D54 FBA_D55 FBA_D56 FBA_D57 FBA_D58 FBA_D59 FBA_D60 FBA_D61 FBA_D62 FBA_D63
net group XDP-MW: nets BP_PWRGD_RST# CR_GPIO0 VCCST_PWRGD_XDP XDP_DBRESET# XDP_PRDY# XDP_PREQ# XDP_RST XDP_SYS_PWROK XDP_TCK_JTAGX XDP_TDI XDP_TDO XDP_TMS XDP_TRST#
net group XDP_BPM-MW: nets XDP_BPM0 XDP_BPM1 XDP_BPM2 XDP_BPM3 XDP_BPM4 XDP_BPM5 XDP_BPM6 XDP_BPM7
net group XDP_TCLK-MW: nets XDP_TCLK
net group XTAL-MW: nets 27MHZ_OUT_R LANXIN LANXOUT RTC_X1 RTC_X2 XTAL24_IN XTAL24_IN_R XTAL24_OUT

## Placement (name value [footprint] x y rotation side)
AFTP2501  AFTE14P-GP  [AFTE14P-75]  27.17 15.04 0 top
AFTP2502  AFTE14P-GP  [AFTE14P-75]  33.36 16.11 270 top
AFTP2801  AFTE14P-GP  [AFTE14P-75]  92.08 136.43 0 top
AFTP2802  AFTE14P-GP  [AFTE14P-75]  92.82 139.17 0 top
AFTP2803  AFTE14P-GP  [AFTE14P-75]  85.03 153.14 0 top
AFTP2901  AFTE14P-GP  [AFTE14P-75]  86.32 4.55 90 top
AFTP2902  AFTE14P-GP  [AFTE14P-75]  86.32 6.58 90 top
AFTP2903  AFTE14P-GP  [AFTE14P-75]  86.32 8.62 90 top
AFTP2904  AFTE14P-GP  [AFTE14P-75]  86.19 10.65 90 top
AFTP3101  AFTE14P-GP  [AFTE14P-75]  15.15 170.01 90 top
AFTP3102  AFTE14P-GP  [AFTE14P-75]  15.31 168.06 90 top
AFTP3103  AFTE14P-GP  [AFTE14P-75]  17.28 166.82 90 top
AFTP3104  AFTE14P-GP  [AFTE14P-75]  17.28 170.29 90 top
AFTP3105  AFTE14P-GP  [AFTE14P-75]  17.14 172.47 90 top
AFTP3106  AFTE14P-GP  [AFTE14P-75]  15.16 172.43 90 top
AFTP3107  AFTE14P-GP  [AFTE14P-75]  15.32 166.12 90 top
AFTP3108  AFTE14P-GP  [AFTE14P-75]  15.37 174.42 90 top
AFTP3301  AFTE14P-GP  [AFTE14P-75]  20.23 31.63 0 top
AFTP3302  AFTE14P-GP  [AFTE14P-75]  27.16 12.48 0 top
AFTP3303  AFTE14P-GP  [AFTE14P-75]  27.29 19.97 0 top
AFTP3304  AFTE14P-GP  [AFTE14P-75]  27.16 28.1 0 top
AFTP3305  AFTE14P-GP  [AFTE14P-75]  27.16 30 0 top
AFTP3306  AFTE14P-GP  [AFTE14P-75]  27.16 24.29 0 top
AFTP3307  AFTE14P-GP  [AFTE14P-75]  27.16 26.19 0 top
AFTP3308  AFTE14P-GP  [AFTE14P-75]  27.16 7.4 0 top
AFTP3309  AFTE14P-GP  [AFTE14P-75]  27.1 10.3 0 top
AFTP3310  AFTE14P-GP  [AFTE14P-75]  27.16 17.51 0 top
AFTP3401  AFTE14P-GP  [AFTE14P-75]  23.59 43.84 0 top
AFTP3402  AFTE14P-GP  [AFTE14P-75]  16.63 40.27 0 top
AFTP3403  AFTE14P-GP  [AFTE14P-75]  16.68 38.34 0 top
AFTP3801  AFTE14P-GP  [AFTE14P-75]  90.02 159.54 0 top
AFTP3802  AFTE14P-GP  [AFTE14P-75]  103.09 171.54 0 top
AFTP3803  AFTE14P-GP  [AFTE14P-75]  97.64 159.58 0 top
AFTP3805  AFTE14P-GP  [AFTE14P-75]  88.12 159.54 0 top
AFTP3806  AFTE14P-GP  [AFTE14P-75]  95.73 159.58 0 top
AFTP3901  AFTE14P-GP  [AFTE14P-75]  156.01 176.58 0 top
AFTP3902  AFTE14P-GP  [AFTE14P-75]  157.92 176.58 0 top
AFTP3903  AFTE14P-GP  [AFTE14P-75]  159.63 174.65 0 top
AFTP3904  AFTE14P-GP  [AFTE14P-75]  159.83 176.59 0 top
AFTP3905  AFTE14P-GP  [AFTE14P-75]  151.33 175.33 0 top
AFTP3906  AFTE14P-GP  [AFTE14P-75]  144.45 178.76 0 top
AFTP3907  AFTE14P-GP  [AFTE14P-75]  144.55 175.01 0 top
AFTP3908  AFTE14P-GP  [AFTE14P-75]  144.95 173.07 0 top
AFTP3909  AFTE14P-GP  [AFTE14P-75]  173.34 174.7 0 top
AFTP3910  AFTE14P-GP  [AFTE14P-75]  153.57 176 0 top
AFTP5501  AFTE14P-GP  [AFTE14P-75]  18 58.1 0 top
AFTP5502  AFTE14P-GP  [AFTE14P-75]  18.01 60.02 0 top
AFTP5503  AFTE14P-GP  [AFTE14P-75]  18 63.83 0 top
AFTP5504  AFTE14P-GP  [AFTE14P-75]  17.35 72 0 top
AFTP5505  AFTE14P-GP  [AFTE14P-75]  18 61.93 0 top
AFTP5506  AFTE14P-GP  [AFTE14P-75]  17.99 69.58 0 top
AFTP5507  AFTE14P-GP  [AFTE14P-75]  18.04 67.66 0 top
AFTP5508  AFTE14P-GP  [AFTE14P-75]  18.01 65.74 0 top
AFTP5601  AFTE14P-GP  [AFTE14P-75]  189.34 36.81 0 top
AFTP5801  AFTE14P-GP  [AFTE14P-75]  164.83 38.71 0 top
AFTP5802  AFTE14P-GP  [AFTE14P-75]  161.65 52.38 0 top
AFTP5803  AFTE14P-GP  [AFTE14P-75]  178.3 51.35 0 top
AFTP5804  AFTE14P-GP  [AFTE14P-75]  176.28 51.14 0 top
AFTP5805  AFTE14P-GP  [AFTE14P-75]  174.37 51.15 0 top
AFTP5806  AFTE14P-GP  [AFTE14P-75]  160.64 61.57 0 top
AFTP5807  AFTE14P-GP  [AFTE14P-75]  160.54 63.5 0 top
AFTP6101  AFTE14P-GP  [AFTE14P-75]  193.01 175.06 180 top
AFTP6102  AFTE14P-GP  [AFTE14P-75]  190.85 178.97 270 top
AFTP6103  AFTE14P-GP  [AFTE14P-75]  193.08 171.4 180 top
AFTP6104  AFTE14P-GP  [AFTE14P-75]  193.01 176.97 270 top
AFTP6201  AFTE14P-GP  [AFTE14P-75]  191.12 123.3 270 top
AFTP6202  AFTE14P-GP  [AFTE14P-75]  178.8 87.71 270 top
AFTP6203  AFTE14P-GP  [AFTE14P-75]  196.43 105.75 270 top
AFTP6206  AFTE14P-GP  [AFTE14P-75]  184.39 85.12 270 top
AFTP6207  AFTE14P-GP  [AFTE14P-75]  194.66 102.65 0 top
AFTP6208  AFTE14P-GP  [AFTE14P-75]  194.62 100.74 0 top
AFTP6213  AFTE14P-GP  [AFTE14P-75]  195.73 99.19 0 top
AFTP6214  AFTE14P-GP  [AFTE14P-75]  194.64 93.74 270 top
AFTP6215  AFTE14P-GP  [AFTE14P-75]  194.65 97.61 0 top
AFTP6216  AFTE14P-GP  [AFTE14P-75]  194.64 110.27 0 top
AFTP6217  AFTE14P-GP  [AFTE14P-75]  17.25 33.56 0 top
AFTP6218  AFTE14P-GP  [AFTE14P-75]  194.93 91.83 270 top
AFTP6219  AFTE14P-GP  [AFTE14P-75]  196.38 107.63 0 top
AFTP6220  AFTE14P-GP  [AFTE14P-75]  194.64 112.17 270 top
AFTP6221  AFTE14P-GP  [AFTE14P-75]  179.81 85.12 270 top
AFTP6222  AFTE14P-GP  [AFTE14P-75]  181.01 86.59 270 top
AFTP6223  AFTE14P-GP  [AFTE14P-75]  188.35 86.81 270 top
AFTP6224  AFTE14P-GP  [AFTE14P-75]  186.14 86.8 270 top
AFTP6225  AFTE14P-GP  [AFTE14P-75]  196.3 101.65 270 top
AFTP6226  AFTE14P-GP  [AFTE14P-75]  194.64 104.55 270 top
AFTP6227  AFTE14P-GP  [AFTE14P-75]  194.68 95.67 0 top
AFTP6228  AFTE14P-GP  [AFTE14P-75]  183.4 87.05 270 top
AFTP6229  AFTE14P-GP  [AFTE14P-75]  194.61 108.36 0 top
AFTP6230  AFTE14P-GP  [AFTE14P-75]  193.25 90.93 270 top
AFTP6231  AFTE14P-GP  [AFTE14P-75]  189.75 85.23 0 top
AFTP6232  AFTE14P-GP  [AFTE14P-75]  196.42 109.56 0 top
AFTP6233  AFTE14P-GP  [AFTE14P-75]  194.64 106.46 0 top
AFTP6234  AFTE14P-GP  [AFTE14P-75]  182.48 85.25 0 top
AFTP6235  AFTE14P-GP  [AFTE14P-75]  59.21 81.22 0 top
AFTP6236  AFTE14P-GP  [AFTE14P-75]  59.16 79.28 0 top
AFTP6237  AFTE14P-GP  [AFTE14P-75]  60.92 75.18 0 top
AFTP6238  AFTE14P-GP  [AFTE14P-75]  60.91 80.2 0 top
AFTP6239  AFTE14P-GP  [AFTE14P-75]  60.92 73.27 0 top
AFTP6240  AFTE14P-GP  [AFTE14P-75]  59.12 74.04 0 top
AFTP6241  AFTE14P-GP  [AFTE14P-75]  59.74 76.69 0 top
AFTP6242  AFTE14P-GP  [AFTE14P-75]  60.92 78.23 0 top
AFTP6243  AFTE14P-GP  [AFTE14P-75]  197.01 111.41 0 top
AFTP6245  AFTE14P-GP  [AFTE14P-75]  186.95 44.09 0 top
AFTP6246  AFTE14P-GP  [AFTE14P-75]  189.42 124.19 0 top
AFTP6247  AFTE14P-GP  [AFTE14P-75]  191.43 126.01 0 top
AFTP6248  AFTE14P-GP  [AFTE14P-75]  191.12 121.37 0 top
AFTP6301  AFTE14P-GP  [AFTE14P-75]  187.58 41.32 0 top
AFTP6302  AFTE14P-GP  [AFTE14P-75]  189.36 41.99 0 top
AFTP6303  AFTE14P-GP  [AFTE14P-75]  187.43 37.9 0 top
AFTP6304  AFTE14P-GP  [AFTE14P-75]  189.37 39.6 0 top
AFTP6305  AFTE14P-GP  [AFTE14P-75]  189.36 23.93 0 top
AFTP6306  AFTE14P-GP  [AFTE14P-75]  189.36 28.07 0 top
AFTP6307  AFTE14P-GP  [AFTE14P-75]  189.31 21.98 0 top
AFTP6309  AFTE14P-GP  [AFTE14P-75]  187.48 26.93 0 top
AFTP6310  AFTE14P-GP  [AFTE14P-75]  187.64 24.74 0 top
AFTP6311  AFTE14P-GP  [AFTE14P-75]  189.29 33.08 0 top
AFTP6313  AFTE14P-GP  [AFTE14P-75]  187.64 28.88 0 top
AFTP6314  AFTE14P-GP  [AFTE14P-75]  188.9 44.08 0 top
BATT1  SYN-CON8-9-GP-U  [200277MR008G121ZR-U]  159.05 179.77 0 bottom
C701  SC22U6D3V5MX-2GP  [C805H58]  120.3 84.58 270 top
C702  SCD1U16V2KX-3GP  [C402H22]  98.92 99.82 180 top
C703  SC1U10V2KX-1GP  [C402H22]  120.47 85.89 270 top
C1001  SC10U6D3V3MX-GP  [C603H38]  113.27 38.51 0 top
C1002  SC10U6D3V3MX-GP  [C603H38]  112.38 83.32 180 top
C1003  SC10U6D3V3MX-GP  [C603H38]  90.81 62.04 270 top
C1004  SC10U10V5KX-2GP  [C805H54]  117.93 83.25 180 top
C1005  SC10U10V5KX-2GP  [C805H54]  114.24 83.27 180 top
C1006  SC10U10V5KX-2GP  [C805H54]  116.08 83.26 180 top
C1017  SC2D2U6D3V2MX-GP  [C402H22]  119.34 79.76 90 top
C1018  SC2D2U6D3V2MX-GP  [C402H22]  111.89 80.09 270 top
C1019  SC2D2U6D3V2MX-GP  [C402H22]  116.26 79.77 90 top
C1020  SC2D2U6D3V2MX-GP  [C402H22]  121.04 79.63 90 top
C1101  SC1U10V2KX-1GP  [C402H22]  136.48 93.3 90 top
C1102  SC1U10V2KX-1GP  [C402H22]  136.48 92.45 90 top
C1103  SC1U10V2KX-1GP  [C402H22]  131.16 101.71 270 bottom
C1104  SC10U10V5KX-2GP  [C805H54]  132.32 104.93 270 bottom
C1105  SC1U10V2KX-1GP  [C402H22]  132.88 101.69 90 bottom
C1106  SC10U10V5KX-2GP  [C805H54]  136.17 104.96 90 bottom
C1107  SC10U10V5KX-2GP  [C805H54]  136.17 103.1 90 bottom
C1108  SC10U10V5KX-2GP  [C805H54]  153.39 72.8 0 bottom
C1109  SC1U10V2KX-1GP  [C402H22]  125.46 85.59 90 top
C1110  SC10U10V5KX-2GP  [C805H54]  127.36 108.61 90 top
C1111  SC1U10V2KX-1GP  [C402H22]  124.34 89.51 0 top
C1112  SC10U10V5KX-2GP  [C805H54]  132.49 104.45 90 top
C1113  SC1U10V2KX-1GP  [C402H22]  128.56 102.87 270 top
C1114  SC10U10V5KX-2GP  [C805H54]  129.58 104.24 270 top
C1115  SC10U10V5KX-2GP  [C805H54]  120.33 82.73 270 top
C1116  SC1U10V2KX-1GP  [C402H22]  125.86 81.94 180 top
C1117  SC1U10V2KX-1GP  [C402H22]  137.73 105.76 90 top
C1118  SC1U10V2KX-1GP  [C402H22]  137.73 104.92 90 top
C1119  SC10U10V5KX-2GP  [C805H54]  134.88 110.04 180 top
C1120  SCD1U16V2KX-3GP  [C402H22]  137.44 60.87 90 top
C1121  SCD1U16V2KX-3GP  [C402H22]  131.57 73.3 90 top
C1122  SC1U10V2KX-1GP  [C402H22]  137.42 61.71 90 top
C1123  SC10U10V5KX-2GP  [C805H54]  132.32 103.03 270 bottom
C1124  SC10U10V5KX-2GP  [C805H54]  127.36 106.76 90 top
C1125  SC10U10V5KX-2GP  [C805H54]  132.47 102.62 90 top
C1201  SCD1U16V2KX-3GP  [C402H22]  91.91 23.79 0 top
C1202  SCD1U16V2KX-3GP  [C402H22]  91.09 23.79 0 top
C1203  SCD1U16V2KX-3GP  [C402H22]  122.33 38.15 0 top
C1204  SCD1U16V2KX-3GP  [C402H22]  60.79 40.9 90 top
C1205  SC2D2U10V3KX-1GP  [C603H36]  60.79 38.96 90 top
C1206  SCD1U16V2KX-3GP  [C402H22]  60.8 40.04 90 top
C1207  SC10U10V5KX-2GP  [C805H54]  90.77 58.23 270 top
C1208  SC10U10V5KX-2GP  [C805H54]  111.36 38.51 0 top
C1209  SC10U6D3V3MX-GP  [C603H38]  119.32 30.09 180 top
C1210  SCD1U16V2KX-3GP  [C402H22]  85.65 30.26 180 top
C1211  SCD1U16V2KX-3GP  [C402H22]  90.42 36.81 0 top
C1212  SC1U10V2KX-1GP  [C402H22]  85.74 36.63 0 top
C1213  SC1U10V2KX-1GP  [C402H22]  89.07 36.88 0 top
C1214  SC1U10V2KX-1GP  [C402H22]  123.38 35.83 270 top
C1215  SC1U10V2KX-1GP  [C402H22]  123.38 34.94 270 top
C1216  SC1U10V2KX-1GP  [C402H22]  123.43 33.3 270 top
C1217  SCD1U16V2KX-3GP  [C402H22]  68.52 31.75 180 top
C1218  SCD1U16V2KX-3GP  [C402H22]  90.26 23.79 0 top
C1220  SCD1U16V2KX-3GP  [C402H22]  89.17 30.26 180 top
C1221  SCD1U16V2KX-3GP  [C402H22]  83.77 37 0 top
C1222  SCD1U16V2KX-3GP  [C402H22]  90.89 30.23 180 top
C1301  SCD1U16V2KX-3GP  [C402H22]  105.67 16.38 180 top
C1302  SCD1U16V2KX-3GP  [C402H22]  90.54 22 270 top
C1303  SC1U10V2KX-1GP  [C402H22]  156.94 17.61 270 top
C1304  SC1U10V2KX-1GP  [C402H22]  156.94 16.78 270 top
C1305  SC2D2U10V3KX-1GP  [C603H36]  90.63 20.11 270 top
C1306  SCD1U16V2KX-3GP  [C402H22]  137.89 16.03 180 top
C1307  SC1U10V2KX-1GP  [C402H22]  157.11 25.33 270 top
C1308  SCD1U16V2KX-3GP  [C402H22]  137.05 16.02 180 top
C1309  SCD1U16V2KX-3GP  [C402H22]  136.2 16.01 180 top
C1310  SCD1U16V2KX-3GP  [C402H22]  90.54 21.16 270 top
C1311  SCD1U16V2KX-3GP  [C402H22]  155.81 25.81 0 top
C1312  SC1U10V2KX-1GP  [C402H22]  117.86 24.99 270 top
C1313  SC1U10V2KX-1GP  [C402H22]  132.85 24.6 0 top
C1314  SCD1U16V2KX-3GP  [C402H22]  119.46 22.92 0 top
C1315  SC10U6D3V3MX-GP  [C603H38]  137.01 29.24 0 top
C1316  SCD1U16V2KX-3GP  [C402H22]  129.1 16.88 180 top
C1317  SCD1U16V2KX-3GP  [C402H22]  128.62 24.89 0 top
C1318  SC10U10V5KX-2GP  [C805H54]  121.86 31.31 180 top
C1319  SCD1U16V2KX-3GP  [C402H22]  121.86 16.88 180 top
C1320  SCD1U16V2KX-3GP  [C402H22]  125.44 16.9 180 top
C1321  SC10U10V5KX-2GP  [C805H54]  90.77 60.13 270 top
C1601  SCD1U16V2KX-3GP  [C402H22]  113.24 102.16 180 bottom
C1602  SCD1U16V2KX-3GP  [C402H22]  112.35 102.16 180 bottom
C1603  SCD1U16V2KX-3GP  [C402H22]  123.33 104.4 180 bottom
C1604  SCD1U16V2KX-3GP  [C402H22]  122.35 104.4 180 bottom
C1605  SCD1U16V2KX-3GP  [C402H22]  127.88 106.07 180 bottom
C1606  SCD1U16V2KX-3GP  [C402H22]  126.99 106.07 180 bottom
C1607  SCD1U16V2KX-3GP  [C402H22]  126.79 104.08 180 bottom
C1608  SCD1U16V2KX-3GP  [C402H22]  125.9 104.08 180 bottom
C1609  SCD1U16V2KX-3GP  [C402H22]  130.44 106.56 180 bottom
C1610  SCD1U16V2KX-3GP  [C402H22]  129.55 106.56 180 bottom
C1611  SCD1U16V2KX-3GP  [C402H22]  129.24 104.36 180 bottom
C1612  SCD1U16V2KX-3GP  [C402H22]  128.36 104.37 180 bottom
C1701  SC220P50V2KX-3GP  [C402H22]  149.86 94.82 90 bottom
C1801  SC15P50V2JN-2-GP  [C402H22]  122.69 107.57 270 bottom
C1802  SC15P50V2JN-2-GP  [C402H22]  124.57 107.57 90 bottom
C1901  SC1U10V2KX-1GP  [C402H22]  143.7 64.42 90 top
C1902  SC1U10V2KX-1GP  [C402H22]  141.98 64.41 270 top
C1903  SC15P50V2JN-2-GP  [C402H22]  149.73 67.66 180 bottom
C1904  SC15P50V2JN-2-GP  [C402H22]  149.74 65.79 0 bottom
C2101  SCD47U6D3V2KX-GP  [C402H22]  127.35 80.24 270 top
C2104  SC1U10V2KX-1GP  [C402H22]  147.98 99.29 0 top
C2105  SC1U10V2KX-1GP  [C402H22]  138.63 105.27 90 bottom
C2109  SC1U10V2KX-1GP  [C402H22]  124.83 74.26 270 top
C2110  SCD1U16V2KX-3GP  [C402H22]  153.12 86.19 270 bottom
C2114  SC1U10V2KX-1GP  [C402H22]  123.38 80.14 270 top
C2116  SC1U10V2KX-1GP  [C402H22]  126.99 73.96 90 top
C2123  SC10U6D3V3MX-GP  [C603H38]  146.67 100.79 270 top
C2128  SC1U10V2KX-1GP  [C402H22]  131.3 100.36 0 top
C2135  SC1U10V2KX-1GP  [C402H22]  144.52 115.67 270 bottom
C2136  SCD1U16V2KX-3GP  [C402H22]  145.4 64.19 90 top
C2137  SC1U10V2KX-1GP  [C402H22]  133.46 105.79 270 top
C2138  SC1U10V2KX-1GP  [C402H22]  127.19 103.76 90 top
C2141  SC4D7U6D3V3KX-GP  [C603H36]  144.13 114.45 270 bottom
C2142  SC10U10V5KX-2GP  [C805H54]  146.08 108.46 180 bottom
C2147  SCD1U16V2KX-3GP  [C402H22]  184.88 71.45 180 bottom
C2401  SCD1U16V2KX-3GP  [C402H22]  195.1 72.99 90 top
C2402  SCD1U16V2KX-3GP  [C402H22]  178.21 64.01 90 top
C2403  SCD1U16V2KX-3GP  [C402H22]  175.06 64.7 180 top
C2404  SCD1U16V2KX-3GP  [C402H22]  179.9 65.12 90 top
C2405  SC2D2U10V3KX-1GP  [C603H36]  180.27 64.04 90 top
C2406  SCD1U16V2KX-3GP  [C402H22]  194.77 77.9 0 top
C2407  SCD1U16V2KX-3GP  [C402H22]  173.31 70.41 270 top
C2408  SCD1U16V2KX-3GP  [C402H22]  186.56 64.87 0 top
C2409  SCD1U16V2KX-3GP  [C402H22]  177.72 76.1 180 bottom
C2410  SCD1U16V2KX-3GP  [C402H22]  192.73 85 180 bottom
C2411  SC2D2U6D3V2MX-GP  [C402H22]  195.86 78.42 0 top
C2412  SCD1U16V2KX-3GP  [C402H22]  191.79 68.63 90 bottom
C2413  SC2D2U10V3KX-1GP  [C603H36]  191.46 67.58 90 bottom
C2414  SCD1U16V2KX-3GP  [C402H22]  176.94 64.44 180 top
C2415  SC220P50V2KX-3GP  [C402H22]  188.97 72.02 180 bottom
C2416  SC1U10V2KX-1GP  [C402H22]  187.06 84.99 180 top
C2417  SCD1U16V2KX-3GP  [C402H22]  169.17 74.25 90 bottom
C2418  SC1U10V2KX-1GP  [C402H22]  173.74 73.36 180 top
C2421  SC47P50V2JN-3GP  [C402H22]  176.79 74.32 0 bottom
C2422  SC100P50V2JN-3GP  [C402H22]  195.1 73.84 90 top
C2501  SC10U10V5KX-2GP  [C805H54]  146.86 58.4 90 bottom
C2502  SCD1U16V2KX-3GP  [C402H22]  146.73 57.05 90 bottom
C2503  SCD47U6D3V2KX-GP  [C402H22]  29.57 9.3 270 top
C2601  SC10U6D3V3MX-GP  [C603H38]  124.83 112.74 0 top
C2602  SCD1U16V2KX-3GP  [C402H22]  124.57 112.96 180 bottom
C2603  SC2200P50V2KX-2GP  [C402H22]  100.03 138.56 270 bottom
C2604  SC4D7U6D3V3KX-GP  [C603H36]  99.91 139.7 270 bottom
C2605  SCD1U16V2KX-3GP  [C402H22]  95.31 144.72 90 bottom
C2606  SC470P50V3JN-2GP  [C603H36]  52.45 67.26 90 bottom
C2607  SC2200P50V2KX-2GP  [C402H22]  124.57 114.73 0 bottom
C2608  SCD1U16V2KX-3GP  [C402H22]  132.37 110.19 180 bottom
C2609  SCD1U16V2KX-3GP  [C402H22]  132.36 111.9 0 bottom
C2610  SCD1U16V2KX-3GP  [C402H22]  173.49 74.63 90 top
C2611  SC4D7U6D3V3KX-GP  [C603H36]  95.18 145.86 90 bottom
C2612  SCD1U16V2KX-3GP  [C402H22]  133.62 113.18 270 bottom
C2613  SC100P50V2JN-3GP  [C402H22]  182.9 64.81 0 top
C2701  SC4D7U6D3V3KX-GP  [C603H36]  175 20.84 90 bottom
C2702  SC4D7U6D3V3KX-GP  [C603H36]  189.52 18.35 90 bottom
C2703  SC1U10V2KX-1GP  [C402H22]  187.69 12.96 180 bottom
C2704  SC1U10V2KX-1GP  [C402H22]  189.06 13.89 90 bottom
C2705  SC2D2U6D3V2MX-GP  [C402H22]  189.18 17.29 90 bottom
C2706  SC4D7U6D3V3KX-GP  [C603H36]  184.64 9.1 270 bottom
C2707  SCD1U16V2KX-3GP  [C402H22]  179.86 11.39 0 bottom
C2708  SC4D7U6D3V3KX-GP  [C603H36]  178.8 10.79 0 bottom
C2709  SCD1U16V2KX-3GP  [C402H22]  185.02 10.19 270 bottom
C2710  SCD1U16V2KX-3GP  [C402H22]  188.96 21.07 0 bottom
C2711  SC4D7U6D3V3KX-GP  [C603H36]  190.02 21.01 0 bottom
C2712  SC10U6D3V3MX-GP  [C603H38]  188.47 11.06 90 bottom
C2713  SC10U6D3V3MX-GP  [C603H38]  185.4 22.64 0 bottom
C2715  SC4D7U6D3V3KX-GP  [C603H36]  186.54 9.55 180 bottom
C2716  SC4D7U6D3V3KX-GP  [C603H36]  176.99 24.51 0 bottom
C2717  SCD1U16V2KX-3GP  [C402H22]  186.34 14.3 270 top
C2718  SC4D7U6D3V3KX-GP  [C603H36]  175.89 17.7 90 bottom
C2719  SCD1U16V2KX-3GP  [C402H22]  179.75 14.13 270 top
C2720  SCD1U16V2KX-3GP  [C402H22]  177.15 21.5 180 bottom
C2723  SC22P50V2JN-4GP  [C402H22]  175.62 14.13 270 bottom
C2901  SC10U6D3V3MX-GP  [C603H38]  179.18 24.29 0 bottom
C2907  SC4D7U6D3V3KX-GP  [C603H36]  189.47 23.02 270 bottom
C2908  SC4D7U6D3V3KX-GP  [C603H36]  189.47 24.41 270 bottom
C3001  SC15P50V2JN-2-GP  [C402H22]  48.95 173.85 90 top
C3002  SCD1U16V2KX-3GP  [C402H22]  52.84 172.24 90 top
C3003  SCD1U16V2KX-3GP  [C402H22]  46.15 163 0 top
C3004  SC4D7U6D3V3KX-GP  [C603H36]  44.22 163.29 0 top
C3005  SC4D7U6D3V3KX-GP  [C603H36]  54.85 162.87 270 top
C3007  SCD1U16V2KX-3GP  [C402H22]  45.3 162.99 0 top
C3008  SCD1U16V2KX-3GP  [C402H22]  45.03 171.22 270 top
C3009  SCD1U16V2KX-3GP  [C402H22]  54.86 169.75 90 top
C3010  SC4D7U6D3V3KX-GP  [C603H36]  54.96 170.8 90 top
C3011  SC15P50V2JN-2-GP  [C402H22]  47.07 174.25 270 top
C3012  SC4D7U6D3V3KX-GP  [C603H36]  55.51 176.99 180 top
C3013  SCD1U16V2KX-3GP  [C402H22]  62.35 177.54 270 top
C3014  SCD1U16V2KX-3GP  [C402H22]  54.23 164.84 90 top
C3015  SC1U10V2KX-1GP  [C402H22]  61.41 172.61 0 top
C3016  SCD1U16V2KX-3GP  [C402H22]  54.23 165.73 90 top
C3017  SCD1U16V2KX-3GP  [C402H22]  47.99 167.16 0 bottom
C3018  SC1U10V2KX-1GP  [C402H22]  51.05 168.36 90 bottom
C3019  SCD1U16V2KX-3GP  [C402H22]  56.6 176.66 180 top
C3021  SCD1U16V2KX-3GP  [C402H22]  44.43 169.76 270 top
C3022  SCD1U16V2KX-3GP  [C402H22]  45.07 173.77 270 top
C3023  SCD1U16V2KX-3GP  [C402H22]  51.05 167.54 90 bottom
C3024  SCD1U16V2KX-3GP  [C402H22]  46.72 168.35 270 bottom
C3025  SCD1U16V2KX-3GP  [C402H22]  46.72 167.44 270 bottom
C3101  SC100P3KV8JN-2-GP  [C1808H56]  26.02 177.32 270 bottom
C3106  SCD01U50V2KX-1GP  [C402H22]  30.84 169.45 180 top
C3201  SC1U10V2KX-1GP  [C402H22]  14.89 12.5 0 bottom
C3202  SCD1U16V2KX-3GP  [C402H22]  11.41 19.4 90 bottom
C3203  SC4D7U6D3V3KX-GP  [C603H36]  11.23 16.39 90 bottom
C3204  SCD01U50V2KX-1GP  [C402H22]  11.41 18.51 90 bottom
C3205  SCD1U16V2KX-3GP  [C402H22]  11.41 17.48 90 bottom
C3206  SC1U10V2KX-1GP  [C402H22]  14 22.15 0 bottom
C3301  SCD1U16V2KX-3GP  [C402H22]  23.98 15.14 180 bottom
C3302  SC4D7U6D3V3KX-GP  [C603H36]  22.84 15.02 180 bottom
C3303  SC10U10V5KX-2GP  [C805H54]  21.19 15.02 180 bottom
C3403  SCD1U16V2KX-3GP  [C402H22]  27.78 41.05 180 bottom
C3404  SCD1U16V2KX-3GP  [C402H22]  26.89 41.05 180 bottom
C3405  SCD1U16V2KX-3GP  [C402H22]  18.68 42.85 180 bottom
C3406  SCD1U16V2KX-3GP  [C402H22]  184.59 39.04 90 bottom
C3504  SCD1U16V2KX-3GP  [C402H22]  44.31 18.51 0 top
C3507  SCD1U16V2KX-3GP  [C402H22]  19.57 42.85 180 bottom
C3508  SC1U10V2KX-1GP  [C402H22]  20.45 42.85 180 bottom
C3510  SC1U10V2KX-1GP  [C402H22]  28.99 45.88 0 bottom
C3512  SC22U6D3V5MX-2GP  [C805H58]  21.78 42.84 180 bottom
C3513  SC22U6D3V5MX-2GP  [C805H58]  19.43 41.61 0 top
C3515  SC22U6D3V5MX-2GP  [C805H58]  195.17 21.85 90 bottom
C3517  SCD1U16V2KX-3GP  [C402H22]  195.23 23.22 90 bottom
C3518  SC1U10V2KX-1GP  [C402H22]  195.23 24.11 90 bottom
C3601  SC470P50V2KX-3GP  [C402H22]  39.54 13.49 0 top
C3602  SC470P50V2KX-3GP  [C402H22]  40.42 13.49 0 top
C3603  SC10U10V5KX-2GP  [C805H54]  42.81 17.07 180 top
C3604  SCD1U16V2KX-3GP  [C402H22]  164.88 68.48 270 top
C3605  SC10U6D3V3MX-GP  [C603H38]  35.77 16.21 270 top
C3701  SCD022U16V2KX-3GP  [C402H22]  64.27 53.19 270 top
C3702  SCD022U16V2KX-3GP  [C402H22]  61.96 52.35 270 top
C3703  SCD022U16V2KX-3GP  [C402H22]  57.72 54.97 270 top
C3801  SC1U10V2KX-1GP  [C402H22]  185.8 71.44 180 bottom
C3802  SC1U10V2KX-1GP  [C402H22]  160.28 70.2 180 bottom
C5201  SCD1U16V2KX-3GP  [C402H22]  82.42 177.6 0 bottom
C5202  SC1KP50V2KX-1GP  [C402H22]  80.43 177.6 0 bottom
C5203  SCD1U16V2KX-3GP  [C402H22]  81.74 170.54 270 top
C5204  SC4D7U6D3V3KX-GP  [C603H36]  87.18 153.27 270 bottom
C5205  SCD1U50V3KX-GP  [C603H36]  91.73 151.22 270 bottom
C5206  SC1U10V2KX-1GP  [C402H22]  83.24 177.6 180 bottom
C5207  SC4D7U6D3V3KX-GP  [C603H36]  84.01 158.53 180 bottom
C5208  SC10P50V2JN-4GP  [C402H22]  83.58 155.82 180 top
C5209  SCD1U16V2KX-3GP  [C402H22]  82.58 172.24 270 top
C5210  SCD1U16V2KX-3GP  [C402H22]  81.74 169.7 270 top
C5211  SCD1U16V2KX-3GP  [C402H22]  81.74 168.84 270 top
C5212  SCD1U16V2KX-3GP  [C402H22]  82.58 173.08 270 top
C5213  SCD1U16V2KX-3GP  [C402H22]  81.74 168.02 270 top
C5214  SC10P50V2JN-4GP  [C402H22]  83.56 154.13 0 top
C5401  SCD1U16V2KX-3GP  [C402H22]  20.36 68.29 90 top
C5402  SCD1U16V2KX-3GP  [C402H22]  24.37 77.88 90 bottom
C5403  SCD1U16V2KX-3GP  [C402H22]  24.37 76.99 90 bottom
C5404  SCD1U16V2KX-3GP  [C402H22]  24.37 76.1 90 bottom
C5405  SCD1U16V2KX-3GP  [C402H22]  24.37 75.21 90 bottom
C5406  SCD1U16V2KX-3GP  [C402H22]  24.37 73.05 90 bottom
C5407  SCD1U16V2KX-3GP  [C402H22]  24.37 72.04 90 bottom
C5408  SCD1U16V2KX-3GP  [C402H22]  24.37 71.15 90 bottom
C5409  SCD1U16V2KX-3GP  [C402H22]  24.37 73.94 90 bottom
C5501  SCD1U16V2KX-3GP  [C402H22]  33.63 61.16 90 top
C5502  SC10U6D3V3MX-GP  [C603H38]  26.54 65.3 270 bottom
C5503  SCD1U16V2KX-3GP  [C402H22]  26.75 59.38 270 top
C5504  SC2D2U10V3KX-1GP  [C603H36]  26.91 57.31 270 top
C5506  SC4D7P50V2BN-GP  [C402H22]  22.74 58.92 0 top
C5507  SC18P50V2JN-1-GP  [C402H22]  20.36 66.6 90 top
C5509  SC4D7P50V2BN-GP  [C402H22]  22.83 63.9 0 top
C5510  SC3D3P50V2CN-GP  [C402H22]  19.5 61.64 0 top
C5511  SC100P50V2JN-3GP  [C402H22]  29.57 68.46 90 top
C5512  SC4D7P50V2BN-GP  [C402H22]  22.8 61.64 0 top
C5513  SC18P50V2JN-1-GP  [C402H22]  20.36 65.77 90 top
C5514  SC3D3P50V2CN-GP  [C402H22]  19.44 58.92 0 top
C5516  SC100P50V2JN-3GP  [C402H22]  27.87 68.45 270 top
C5517  SCD1U16V2KX-3GP  [C402H22]  32.62 62.15 0 bottom
C5518  SC3D3P50V2CN-GP  [C402H22]  19.58 63.84 0 top
C5519  SCD01U16V2KX-3GP  [C402H22]  20.37 67.44 90 top
C5520  SCD1U16V2KX-3GP  [C402H22]  28.17 66.38 270 bottom
C5521  SC10U6D3V3MX-GP  [C603H38]  23.52 66.05 90 top
C5522  SCD1U16V2KX-3GP  [C402H22]  28.32 58.85 0 top
C5523  SC10U6D3V3MX-GP  [C603H38]  31.57 61.94 180 bottom
C5524  SCD1U16V2KX-3GP  [C402H22]  26.46 66.37 270 bottom
C5525  SCD1U16V2KX-3GP  [C402H22]  39.12 75.79 270 top
C5526  SCD1U16V2KX-3GP  [C402H22]  39.15 73.79 270 top
C5527  SCD1U16V2KX-3GP  [C402H22]  34.64 62.03 270 top
C5528  SCD1U16V2KX-3GP  [C402H22]  34.64 62.89 270 top
C5529  SCD1U16V2KX-3GP  [C402H22]  39.15 72.95 270 top
C5530  SCD1U16V2KX-3GP  [C402H22]  39.12 74.96 270 top
C5601  SC10U10V5KX-2GP  [C805H54]  193.54 38.95 180 bottom
C5602  SCD01U50V2KX-1GP  [C402H22]  182.48 31.98 90 bottom
C5603  SCD01U50V2KX-1GP  [C402H22]  182.48 32.87 90 bottom
C5604  SCD1U16V2KX-3GP  [C402H22]  196.23 38.47 180 bottom
C5605  SC10U10V5KX-2GP  [C805H54]  189.37 35.89 90 bottom
C5606  SCD1U16V2KX-3GP  [C402H22]  189.09 34.48 90 bottom
C5607  SCD01U50V2KX-1GP  [C402H22]  150.63 76.24 270 top
C5608  SCD01U50V2KX-1GP  [C402H22]  150.63 77.07 270 top
C5609  SC10U10V5KX-2GP  [C805H54]  160.13 81.68 0 bottom
C5610  SC10U10V5KX-2GP  [C805H54]  157.34 81.73 0 bottom
C5611  SCD01U50V2KX-1GP  [C402H22]  150.38 75.26 270 top
C5612  SCD01U50V2KX-1GP  [C402H22]  150.38 74.43 270 top
C5615  SCD01U50V2KX-1GP  [C402H22]  181.82 35.03 270 bottom
C5616  SCD01U50V2KX-1GP  [C402H22]  181.82 34.14 270 bottom
C5801  SCD1U16V2KX-3GP  [C402H22]  164.46 35.94 270 top
C5802  SCD1U16V2KX-3GP  [C402H22]  164.46 35.06 270 top
C5803  SCD1U16V2KX-3GP  [C402H22]  169.76 41.52 90 bottom
C5804  SCD1U16V2KX-3GP  [C402H22]  170.61 66.13 0 bottom
C5805  SC10U6D3V3MX-GP  [C603H38]  164.58 37.09 270 top
C5806  SC10U6D3V3MX-GP  [C603H38]  168.38 38.56 0 top
C6201  SCD1U16V2KX-3GP  [C402H22]  52.77 78.23 270 bottom
C6202  SCD1U16V2KX-3GP  [C402H22]  189.59 122.38 180 top
C6203  SCD1U16V2KX-3GP  [C402H22]  187.81 123.93 0 top
C6204  SCD1U16V2KX-3GP  [C402H22]  45.52 77.89 180 top
C7301  SCD22U10V2KX-1GP  [C402H22]  153.59 133.87 90 top
C7302  SCD22U10V2KX-1GP  [C402H22]  153.59 134.76 90 top
C7303  SCD22U10V2KX-1GP  [C402H22]  153.74 135.62 90 top
C7304  SCD22U10V2KX-1GP  [C402H22]  153.74 136.51 90 top
C7305  SCD22U10V2KX-1GP  [C402H22]  154.71 137.41 90 top
C7306  SCD22U10V2KX-1GP  [C402H22]  154.71 138.29 90 top
C7307  SCD22U10V2KX-1GP  [C402H22]  154.59 139.16 90 top
C7308  SCD22U10V2KX-1GP  [C402H22]  154.59 140.05 90 top
C7310  SC4D7U6D3V3KX-GP  [C603H36]  150.14 148.4 0 bottom
C7312  SC1U10V2KX-1GP  [C402H22]  157.59 142.82 0 top
C7315  SC4D7U6D3V3KX-GP  [C603H36]  170.53 138.3 270 top
C7316  SCD1U25V2KX-GP  [C402H22]  161.32 134.81 90 top
C7317  SC4D7U6D3V3KX-GP  [C603H36]  161.14 141.57 90 top
C7318  SCD1U16V2KX-3GP  [C402H22]  161.5 140.49 90 top
C7319  SC1U10V2KX-1GP  [C402H22]  161.49 139.66 90 top
C7323  SC10U6D3V3MX-GP  [C603H38]  147.54 144.91 90 bottom
C7324  SC4D7U6D3V3KX-GP  [C603H36]  161.31 136.04 90 top
C7326  SC22U6D3V5MX-2GP  [C805H58]  149.65 146.09 270 top
C7501  SCD1U16V2KX-3GP  [C402H22]  170.74 150.05 0 top
C7502  SCD1U16V2KX-3GP  [C402H22]  165.21 150.99 180 top
C7505  SCD1U16V2KX-3GP  [C402H22]  163.99 144.35 0 top
C7506  SCD1U16V2KX-3GP  [C402H22]  172.32 141.23 0 top
C7507  SC1U6D3V3KX-2GP  [C603H36]  175.62 143.57 270 top
C7508  SCD1U16V2KX-3GP  [C402H22]  159.54 172.63 180 top
C7509  SCD1U16V2KX-3GP  [C402H22]  151.75 167.75 90 bottom
C7510  SCD1U16V2KX-3GP  [C402H22]  151.75 166.88 90 bottom
C7512  SCD1U16V2KX-3GP  [C402H22]  151.62 170.82 270 top
C7513  SC4D7U6D3V3KX-GP  [C603H36]  170.91 139.59 270 top
C7514  SC4D7U6D3V3KX-GP  [C603H36]  170.92 142.93 270 top
C7517  SC10U10V5KX-2GP  [C805H54]  153.72 151.27 90 top
C7518  SC22U6D3V5MX-2GP  [C805H58]  166.14 144.86 90 top
C7520  SC22U6D3V5MX-2GP  [C805H58]  169.03 144.87 270 top
C7522  SCD1U16V2KX-3GP  [C402H22]  157.08 173.11 0 bottom
C7523  SCD1U16V2KX-3GP  [C402H22]  172.78 174.15 0 bottom
C7524  SCD1U16V2KX-3GP  [C402H22]  166.22 160.61 0 bottom
C7525  SC1U6D3V3KX-2GP  [C603H36]  160.04 152.48 270 top
C7529  SCD1U16V2KX-3GP  [C402H22]  162.35 173.1 0 bottom
C7532  SCD1U16V2KX-3GP  [C402H22]  178.34 174.1 0 bottom
C7533  SCD1U16V2KX-3GP  [C402H22]  151.78 168.67 90 bottom
C7534  SCD1U16V2KX-3GP  [C402H22]  153.82 173.1 0 bottom
C7601  SCD1U16V2KX-3GP  [C402H22]  168.27 131.56 90 top
C7602  SCD1U16V2KX-3GP  [C402H22]  168.13 133.76 90 top
C7603  SC4D7U6D3V3KX-GP  [C603H36]  165.45 134.82 270 top
C7604  SC10U6D3V3MX-GP  [C603H38]  167.83 134.81 90 top
C7605  SCD1U16V2KX-3GP  [C402H22]  170.16 133.13 90 top
C7606  SC2D2U6D3V2MX-GP  [C402H22]  170.16 132.24 90 top
C7607  SC15P50V2JN-2-GP  [C402H22]  181.08 129.44 180 bottom
C7608  SC15P50V2JN-2-GP  [C402H22]  181.08 127.66 0 bottom
C7609  SC2700P50V2KX-1-GP  [C402H22]  189.74 127.58 270 bottom
C7610  SC2700P50V2KX-1-GP  [C402H22]  195.55 122.1 270 bottom
C7701  SC4D7U6D3V3KX-GP  [C603H36]  162.2 126.05 270 top
C7702  SC4D7U6D3V3KX-GP  [C603H36]  160.33 142.98 270 top
C7703  SC4D7U6D3V3KX-GP  [C603H36]  169.58 122.86 90 bottom
C7704  SC4D7U6D3V3KX-GP  [C603H36]  159.55 131.48 90 top
C7708  SC4D7U6D3V3KX-GP  [C603H36]  163.6 135.13 0 top
C7709  SC4D7U6D3V3KX-GP  [C603H36]  162.2 127.45 270 top
C7710  SC22U6D3V5MX-2GP  [C805H58]  181.83 121.29 0 bottom
C7711  SC1U10V2KX-1GP  [C402H22]  169.76 136.79 180 top
C7712  SC1U10V2KX-1GP  [C402H22]  169.3 140.03 0 top
C7713  SC1U10V2KX-1GP  [C402H22]  161.92 143.07 180 top
C7714  SC1U10V2KX-1GP  [C402H22]  169.3 142.22 0 top
C7717  SC22U6D3V5MX-2GP  [C805H58]  183.66 121.29 0 bottom
C7719  SC4D7U6D3V3KX-GP  [C603H36]  163.69 137.52 0 top
C7720  SC4D7U6D3V3KX-GP  [C603H36]  161.8 138.05 0 top
C7721  SC4D7U6D3V3KX-GP  [C603H36]  162.2 128.84 270 top
C7722  SC4D7U6D3V3KX-GP  [C603H36]  165.64 142.34 0 top
C7723  SC4D7U6D3V3KX-GP  [C603H36]  163.68 139.9 0 top
C7724  SC4D7U6D3V3KX-GP  [C603H36]  167.67 139.8 0 top
C7725  SC4D7U6D3V3KX-GP  [C603H36]  163.68 142.31 0 top
C7726  SC4D7U6D3V3KX-GP  [C603H36]  167.67 142.21 0 top
C7728  SC1U10V2KX-1GP  [C402H22]  173.97 133.89 90 top
C7729  SCD1U16V2KX-3GP  [C402H22]  171.05 136.34 270 top
C7730  SC4D7U6D3V3KX-GP  [C603H36]  167.67 137.38 0 top
C7731  SC4D7U6D3V3KX-GP  [C603H36]  165.64 139.92 0 top
C7732  SC4D7U6D3V3KX-GP  [C603H36]  165.63 137.48 0 top
C7734  SCD1U16V2KX-3GP  [C402H22]  171.06 137.16 270 top
C7735  SCD1U16V2KX-3GP  [C402H22]  159.64 130.39 90 top
C7736  SC1U10V2KX-1GP  [C402H22]  159.64 129.54 90 top
C7803  SC820P50V2KX-1GP  [C402H22]  198.31 134.09 270 bottom
C7804  SCD1U16V2KX-3GP  [C402H22]  183.25 143.9 90 top
C7805  SC1U6D3V3KX-2GP  [C603H36]  200.87 151.36 270 bottom
C7810  SC1U6D3V3KX-2GP  [C603H36]  200.85 143.84 270 bottom
C7811  SC1U6D3V3KX-2GP  [C603H36]  200.85 142.46 270 bottom
C7812  SC1U6D3V3KX-2GP  [C603H36]  200.88 150.04 270 bottom
C7814  SC1U6D3V3KX-2GP  [C603H36]  200.89 147.38 270 bottom
C7816  SC1U6D3V3KX-2GP  [C603H36]  193.27 159.13 180 top
C7817  SC1U6D3V3KX-2GP  [C603H36]  200.93 149.28 90 top
C7820  SCD1U16V2KX-3GP  [C402H22]  184.94 143.9 270 top
C7821  SCD1U16V2KX-3GP  [C402H22]  201.29 145.17 90 top
C7822  SC1U6D3V3KX-2GP  [C603H36]  200.89 148.71 270 bottom
C7827  SCD1U16V2KX-3GP  [C402H22]  179.83 143.91 90 top
C7829  SCD1U16V2KX-3GP  [C402H22]  181.53 143.9 270 top
C7830  SCD1U16V2KX-3GP  [C402H22]  198.93 141.99 270 top
C7831  SCD1U16V2KX-3GP  [C402H22]  191.86 158.41 0 bottom
C7832  SCD1U16V2KX-3GP  [C402H22]  201.29 144.33 90 top
C7833  SCD1U16V2KX-3GP  [C402H22]  198.92 142.84 270 top
C7834  SCD1U16V2KX-3GP  [C402H22]  200.79 146.28 270 bottom
C7835  SCD1U16V2KX-3GP  [C402H22]  201.29 146 90 top
C7836  SCD1U16V2KX-3GP  [C402H22]  201.3 143.48 90 top
C7902  SC820P50V2KX-1GP  [C402H22]  180.83 166.5 270 bottom
C7906  SC1U6D3V3KX-2GP  [C603H36]  151.44 168.92 270 top
C7909  SCD1U16V2KX-3GP  [C402H22]  187.02 175.09 0 bottom
C7910  SCD1U16V2KX-3GP  [C402H22]  185.12 173.39 180 top
C7911  SC1U6D3V3KX-2GP  [C603H36]  151.52 164.67 90 bottom
C7912  SCD1U16V2KX-3GP  [C402H22]  166.22 157.08 180 bottom
C7913  SCD1U16V2KX-3GP  [C402H22]  159.18 173.1 0 bottom
C7915  SC1U6D3V3KX-2GP  [C603H36]  182.75 173.74 180 top
C7916  SC1U6D3V3KX-2GP  [C603H36]  151.52 163.38 90 bottom
C7917  SC1U6D3V3KX-2GP  [C603H36]  153.55 172.75 180 top
C7919  SC1U6D3V3KX-2GP  [C603H36]  187.01 173.74 180 top
C7921  SCD1U16V2KX-3GP  [C402H22]  170.8 174.15 0 bottom
C7922  SCD1U16V2KX-3GP  [C402H22]  180.07 174.1 0 bottom
C7923  SCD1U16V2KX-3GP  [C402H22]  201.07 138.71 270 bottom
C7924  SC1U6D3V3KX-2GP  [C603H36]  158.46 172.57 180 top
C7925  SCD1U16V2KX-3GP  [C402H22]  188.67 175.05 0 bottom
C7926  SC1U6D3V3KX-2GP  [C603H36]  151.44 167.53 270 top
C7927  SCD1U16V2KX-3GP  [C402H22]  160.73 173.1 0 bottom
C7928  SCD1U16V2KX-3GP  [C402H22]  171.66 174.17 0 bottom
C7929  SCD1U16V2KX-3GP  [C402H22]  166.22 158.78 0 bottom
C7930  SCD1U16V2KX-3GP  [C402H22]  160.37 172.65 180 top
C8001  SCD1U16V2KX-3GP  [C402H22]  184.82 143.86 90 bottom
C8002  SCD1U16V2KX-3GP  [C402H22]  190.79 158.27 180 top
C8003  SC1U6D3V3KX-2GP  [C603H36]  200.89 141.12 270 bottom
C8004  SCD1U16V2KX-3GP  [C402H22]  189.65 175.03 0 bottom
C8005  SCD1U16V2KX-3GP  [C402H22]  198.28 139.65 90 bottom
